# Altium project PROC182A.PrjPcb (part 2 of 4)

## Sheet PROC182A_Decoupling_caps- QSPI Flash.SchDoc: DECOUPLING_CAPS
size 431 x 279 mm; Date: Not shown in title block; ApprovedBy: Not shown in title block; CheckedBy: Not shown in title block; Author: Not shown in title block; CompanyName: Not shown in title block; DrawnBy: Mistral; Engineer: Not shown in title block; Organization: Not shown in title block; Address1: Not shown in title block; Address2: Not shown in title block; Address3: Not shown in title block; Address4: Not shown in title block; DocumentNumber: 2; Revision: Use project parameter SCH_Rev; SheetNumber: 7; SheetTotal: 17; PageSetup: Record=PageOptions¦CenterHorizontal=True¦CenterVertical=True¦PrintScale=1.00¦XCorrection=1.00¦YCorrection=1.00¦PrintKind=0¦BorderSize=5000000¦LeftOffset=0¦BottomOffset=0¦Orientation=2¦PaperLength=1000¦PaperWidth=1000¦Scale=100¦PaperSource=15¦PrintQuality=600¦MediaType=1¦DitherType=10¦PaperKind=Letter¦PrintScaleMode=1
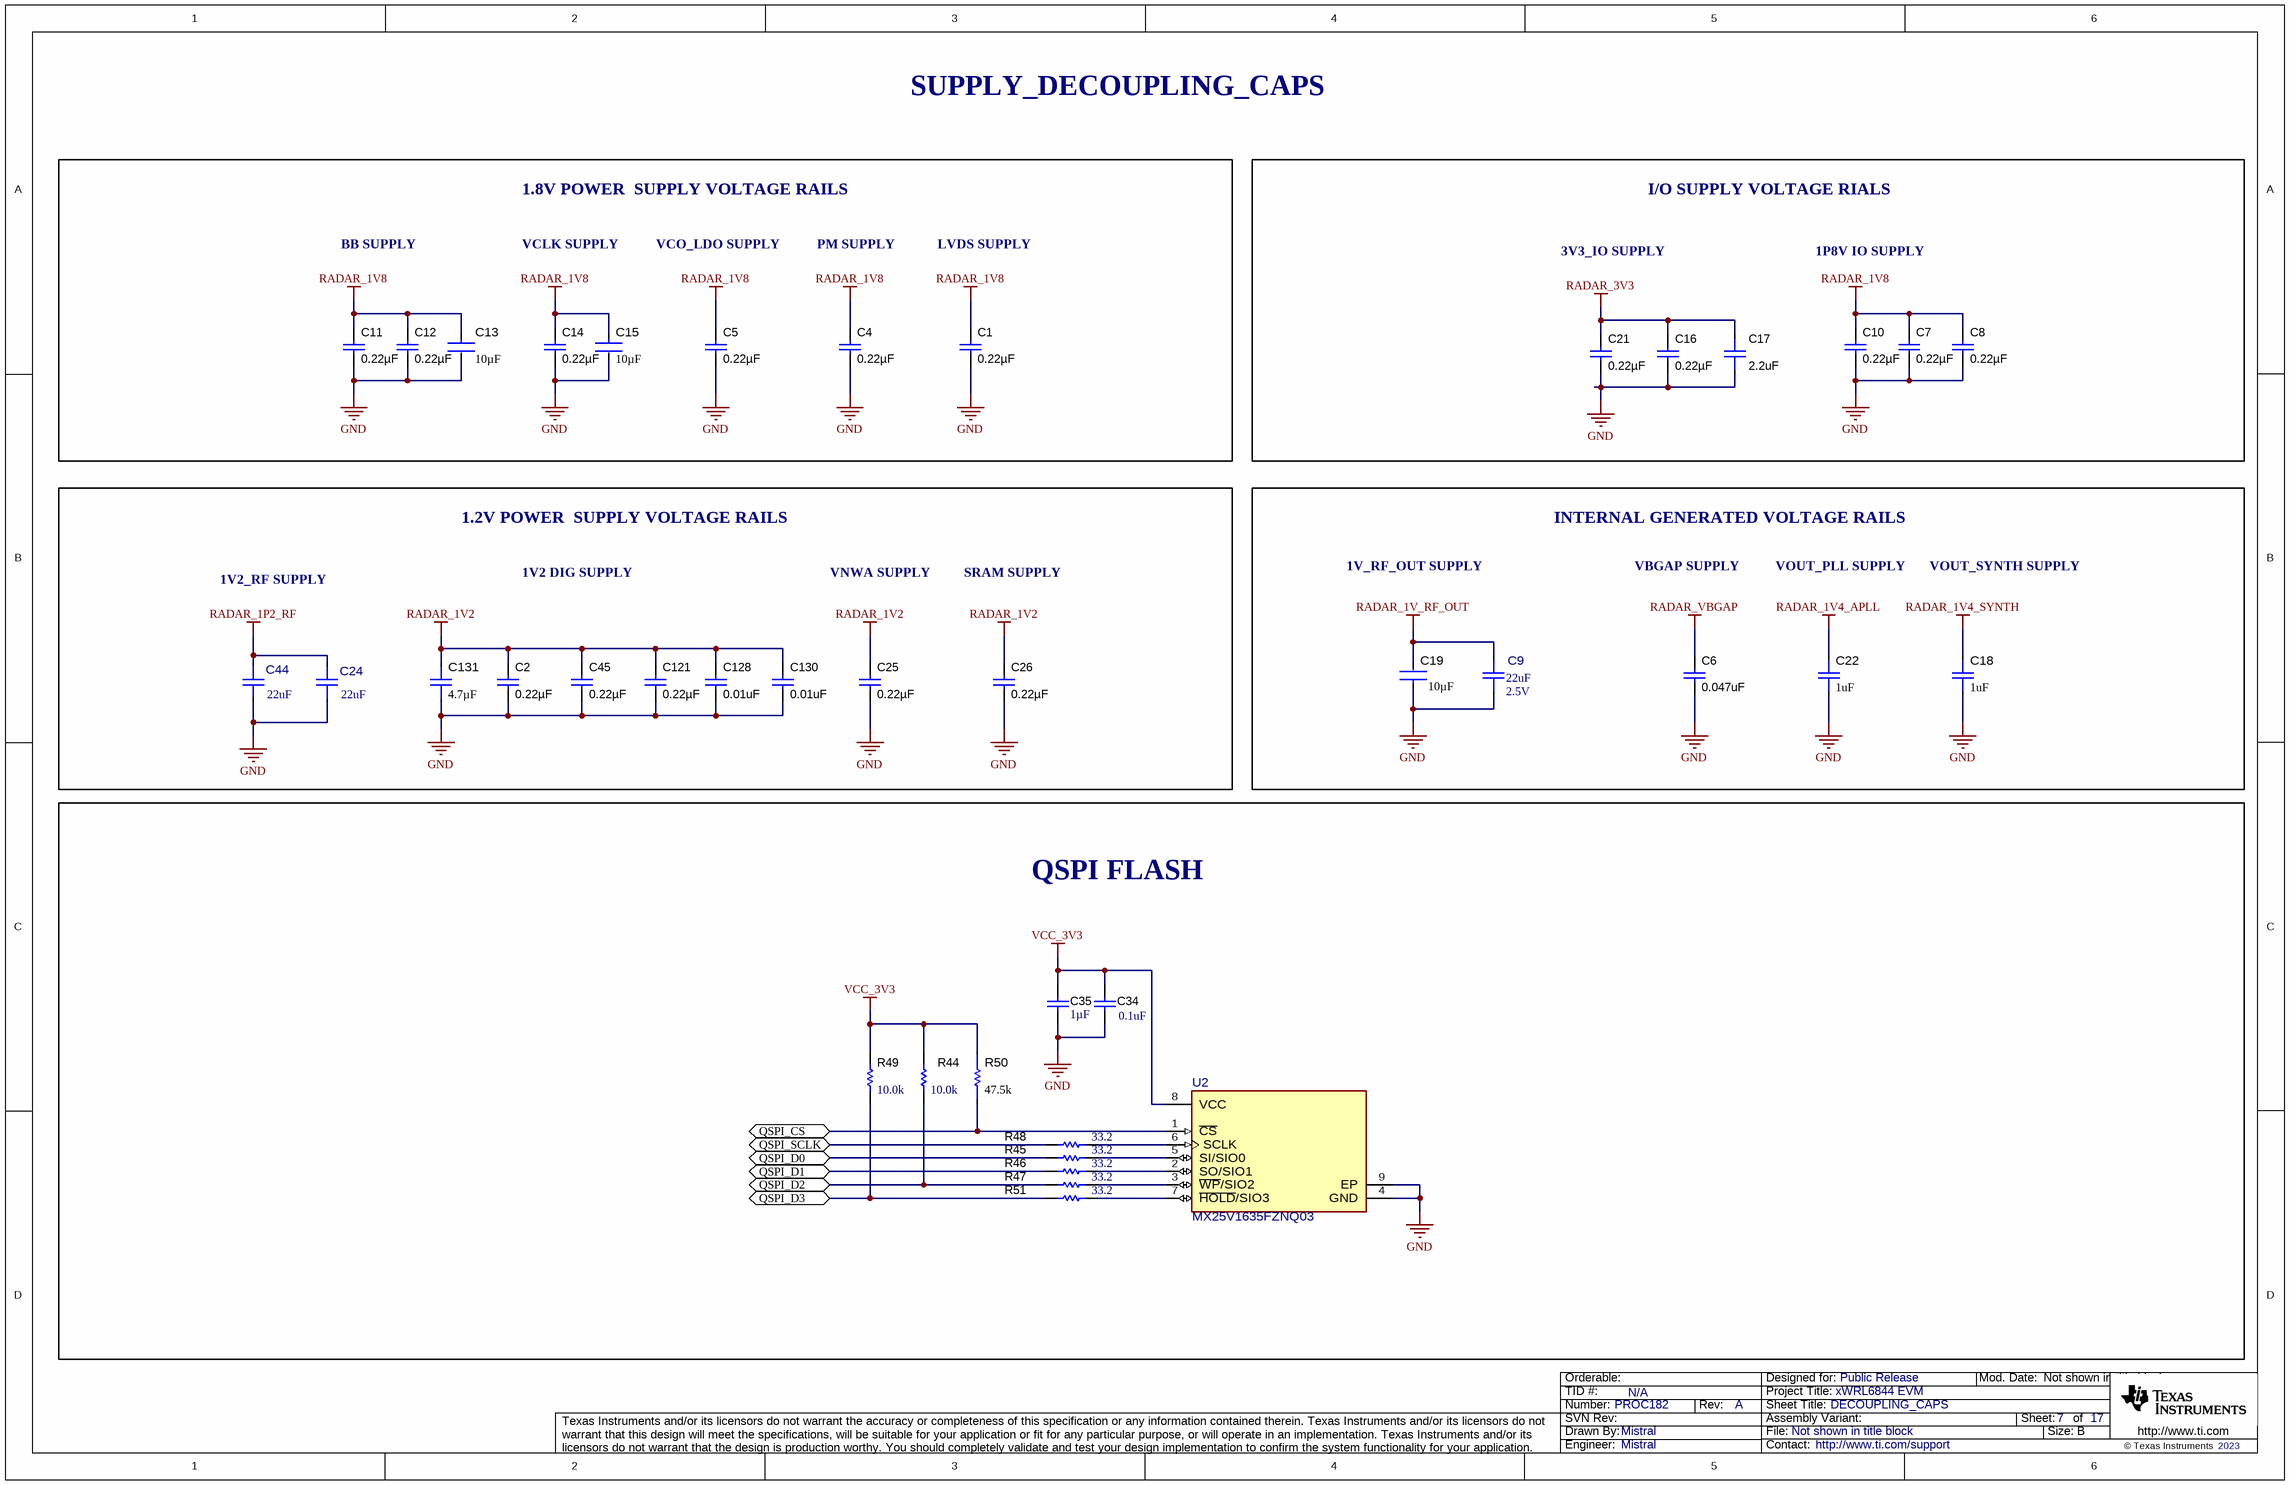
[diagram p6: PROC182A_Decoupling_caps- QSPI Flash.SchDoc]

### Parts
C1  ValueDisplayed: 0.22µF  [0402L]  (hidden comment: GCM155R71C224KE02D)
C2  ValueDisplayed: 0.22µF  [0402L]  (hidden comment: GCM155R71C224KE02D)
C4  ValueDisplayed: 0.22µF  [0402L]  (hidden comment: GCM155R71C224KE02D)
C5  ValueDisplayed: 0.22µF  [0402L]  (hidden comment: GCM155R71C224KE02D)
C6  ValueDisplayed: 0.047uF  [0402L]  (hidden comment: CGA2B3X7R1H473K050BB)
C7  ValueDisplayed: 0.22µF  [0402L]  (hidden comment: GCM155R71C224KE02D)
C8  ValueDisplayed: 0.22µF  [0402L]  (hidden comment: GCM155R71C224KE02D)
C9  ValueDisplayed: 22uF  VDC_V: 2.5V  [FP-GCM188D70E226ME36D_0603-MFG]  (hidden comment: GCM188D70E226ME36D)
C10  ValueDisplayed: 0.22µF  [0402L]  (hidden comment: GCM155R71C224KE02D)
C11  ValueDisplayed: 0.22µF  [0402L]  (hidden comment: GCM155R71C224KE02D)
C12  ValueDisplayed: 0.22µF  [0402L]  (hidden comment: GCM155R71C224KE02D)
C13  Cap_F: 10µF  [FP-GCM188D70J106ME36D_0603-MFG]  (hidden comment: GCM188D70J106ME36D)
C14  ValueDisplayed: 0.22µF  [0402L]  (hidden comment: GCM155R71C224KE02D)
C15  Cap_F: 10µF  [FP-GCM188D70J106ME36D_0603-MFG]  (hidden comment: GCM188D70J106ME36D)
C16  ValueDisplayed: 0.22µF  [0402L]  (hidden comment: GCM155R71C224KE02D)
C17  ValueDisplayed: 2.2uF  [FP-GRT155C71A225KE13D_0402-MFG]  (hidden comment: GRT155C71A225KE13D)
C18  ValueDisplayed: 1uF  [FP-GRT155R70J105KE01D_0402-MFG]  (hidden comment: GRT155R70J105KE01D)
C19  Cap_F: 10µF  [FP-GCM188D70J106ME36D_0603-MFG]  (hidden comment: GCM188D70J106ME36D)
C21  ValueDisplayed: 0.22µF  [0402L]  (hidden comment: GCM155R71C224KE02D)
C22  ValueDisplayed: 1uF  [FP-GRT155R70J105KE01D_0402-MFG]  (hidden comment: GRT155R70J105KE01D)
C24  ValueDisplayed: 22uF  [FP-GCM188D70E226ME36D_0603-MFG]  (hidden comment: GCM188D70E226ME36D)
C25  ValueDisplayed: 0.22µF  [0402L]  (hidden comment: GCM155R71C224KE02D)
C26  ValueDisplayed: 0.22µF  [0402L]  (hidden comment: GCM155R71C224KE02D)
C34  ValueDisplayed: 0.1uF  [0402]  (hidden comment: GCM155R71H104KE02D)
C35  Cap_F: 1µF  [0603]  (hidden comment: CL10B105KA8NNNC)
C44  ValueDisplayed: 22uF  [FP-GCM188D70E226ME36D_0603-MFG]  (hidden comment: GCM188D70E226ME36D)
C45  ValueDisplayed: 0.22µF  [0402L]  (hidden comment: GCM155R71C224KE02D)
C121  ValueDisplayed: 0.22µF  [0402L]  (hidden comment: GCM155R71C224KE02D)
C128  ValueDisplayed: 0.01uF  [0402L]  (hidden comment: GCM155R71E103KA37D)
C130  ValueDisplayed: 0.01uF  [0402L]  (hidden comment: GCM155R71E103KA37D)
C131  Cap_F: 4.7µF  [FP-GCJ21BR71C475KA01L_0805-MFG]  (hidden comment: GCJ21BR71C475KA01L)
R44  value 10.0k  [0402]  (hidden comment: CRCW040210K0FKED)
R45  value 33.2  [0402]  (hidden comment: CRCW040233R2FKED)
R46  value 33.2  [0402]  (hidden comment: CRCW040233R2FKED)
R47  value 33.2  [0402]  (hidden comment: CRCW040233R2FKED)
R48  value 33.2  [0402]  (hidden comment: CRCW040233R2FKED)
R49  value 10.0k  [0402]  (hidden comment: CRCW040210K0FKED)
R50  value 47.5k  [FP-RC0402FR-1047K5L_0402-MFG]  (hidden comment: RC0402FR-1047K5L)
R51  value 33.2  [0402]  (hidden comment: CRCW040233R2FKED)
U2  MX25V1635FZNQ03  [FP-MX25V1635FZNQ03_WSON8-MFG]

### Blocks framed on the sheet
1.8V POWER  SUPPLY VOLTAGE RAILS: C1 C4 C5 C11-C15
I/O SUPPLY VOLTAGE RIALS: C7 C8 C10 C16 C17 C21
1.2V POWER  SUPPLY VOLTAGE RAILS: C2 C24-C26 C44 C45 C121 C128 C130 C131
INTERNAL GENERATED VOLTAGE RAILS: C6 C9 C18 C19 C22
QSPI FLASH: C34 C35 R44-R51 U2

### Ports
QSPI_CS (bidir), QSPI_D0 (bidir), QSPI_D1 (bidir), QSPI_D2 (bidir), QSPI_D3 (bidir), QSPI_SCLK (bidir)

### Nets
GND: C1.1 C2.1 C4.1 C5.1 C6.2 C7.1 C8.1 C9.1 C10.1 C11.1 C12.1 C13.2 C14.1 C15.2 C16.1 C17.1 C18.1 C19.1 C21.1 C22.1 C24.1 C25.1 C26.1 C34.2 C35.1 C44.2 C45.1 C121.1 C128.2 C130.2 C131.1 U2.4(GND) U2.9(EP)
RADAR_1P2_RF: C24.2 C44.1
RADAR_1V2: C2.2 C25.2 C26.2 C45.2 C121.2 C128.1 C130.1 C131.2
RADAR_1V4_APLL: C22.2
RADAR_1V4_SYNTH: C18.2
RADAR_1V8: C1.2 C4.2 C5.2 C7.2 C8.2 C10.2 C11.2 C12.2 C13.1 C14.2 C15.1
RADAR_1V_RF_OUT: C9.2 C19.2
RADAR_3V3: C16.2 C17.2 C21.2
RADAR_VBGAP: C6.1
VCC_3V3: C34.1 C35.2 R44.2 R49.2 R50.1 U2.8(VCC)
QSPI_CS: R50.2 U2.1(~{CS}) ; port QSPI_CS
QSPI_D0: R45.2 ; port QSPI_D0
QSPI_D1: R46.1 ; port QSPI_D1
QSPI_D2: R44.1 R47.1 ; port QSPI_D2
QSPI_D3: R49.1 R51.2 ; port QSPI_D3
QSPI_SCLK: R48.2 ; port QSPI_SCLK
NetR45_1: R45.1 U2.5(SI/SIO0)
NetR46_2: R46.2 U2.2(SO/SIO1)
NetR47_2: R47.2 U2.3(~{WP}/SIO2)
NetR48_1: R48.1 U2.6(SCLK)
NetR51_1: R51.1 U2.7(~{HOLD}/SIO3)

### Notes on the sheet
- SUPPLY_DECOUPLING_CAPS
- BB SUPPLY
- VCLK SUPPLY
- VCO_LDO SUPPLY
- PM SUPPLY
- LVDS SUPPLY
- 3V3_IO SUPPLY
- 1P8V IO SUPPLY
- 1V_RF_OUT SUPPLY
- VBGAP SUPPLY
- VOUT_PLL SUPPLY
- VOUT_SYNTH SUPPLY
- 1V2_RF SUPPLY
- 1V2 DIG SUPPLY
- VNWA SUPPLY
- SRAM SUPPLY

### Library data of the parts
C1 C2 C4 C5 C7 C8 C10-C12 C14 C16 C21 C25 C26 C45 C121 = CMP-0078265-1: CAP, CERM, 0.22 µF, 16 V,+/- 10%, X7R, AEC-Q200 Grade 1, 0402; Manufacturer: MuRata; TaMin_C: -55°C; Polarized: N; SizeAreaWB_mm2: 3; U/M: EA; Value: 0.22uF; TaMax_C: 125°C; SizeZ_mm: 0.6; SizeX_mm: 1; SizeY_mm: 0.5; Cap_Case: 0402; Value2: 16V; CompType: Capacitor; AEC Qualified: Y; Cap_F: 220nF; AEC Category: Q200
C6 = CMP-0006330-2: CAP, CERM, 0.047 uF, 50 V, +/- 10%, X7R, AEC-Q200 Grade 1, 0402; Manufacturer: TDK; Polarized: N; U/M: EA; Cap_F: 47nF; ESR_ohm: 0.06407; Value1: 0.06407 ohm; VDC_V: 50V; IRMS_A: 646.122mA; TaMin_C: -55°C; TaMax_C: 125°C; Cap_Case: 0402; SizeArea_mm2: 0.5; SizeAreaWB_mm2: 3; SizeX_mm: 1; SizeZ_mm: 0.6; AEC Category: Q200; AEC Qualified: Y
C9 C24 C44 = CMP-0048366-1: 22 µF ±20% 2.5V Ceramic Capacitor X7T 0603 (1608 Metric); Manufacturer: Murata; AEC Grade: Grade 1; AEC Qualified: Yes; Cap_F: 22µF; SizeZ_mm: 1mm; TempCo: +22/-33%; Value: 22µF
C13 C15 C19 = CMP-0086534-1: Chip Multilayer Ceramic Capacitors for Automotive; Manufacturer: Murata; Tolerance_%: 20%; SizeZ_mm: 1mm; TempCo: -33+22%; Symbol Name: SYM-GCM188D70J106ME36D; VDC_V: 6.3V; AEC Grade: Grade 1; AEC Qualified: Yes
C17 = CMP-0094968-1: Multi-Layer Ceramic Capacitor 2.2uF 10V X7S ±10% 0402 Paper T/R; Manufacturer: Murata; AEC Grade: Grade 1; Cap_F: 2.2µF; SizeZ_mm: 0.7mm; Value: 2.2µF; AEC Qualified: Yes; TempCo: 22%
C18 C22 = CMP-0088425-1: 1µF ±10% 6.3V Ceramic Capacitor X7R 0402 (1005 Metric); Manufacturer: Murata; AEC Grade: Grade 1; SizeZ_mm: 0.55mm; AEC Qualified: Yes; TempCo: 15%
C34 = CMP-0006356-2: CAP, CERM, 0.1 uF, 50 V, +/- 10%, X7R, AEC-Q200 Grade 1, 0402; Manufacturer: MuRata; TaMin_C: -55°C; Polarized: N; SizeAreaWB_mm2: 3; Value1: Unknown; U/M: EA; Value: 0.1uF; TaMax_C: 125°C; SizeZ_mm: 0.6; SizeX_mm: 1; SizeY_mm: 0.5; Value2: 50V; AEC Qualified: Y; Cap_F: 100nF; AEC Category: Q200
C35 = CMP-0086540-3: CAP, 1uF, 25V, ±10%, X7R, 0603; Manufacturer: Samsung; SizeZ_mm: 0.9mm; AEC Qualified: No; TempCo: 15%; Symbol Name: SYM-CL10B105KA8NNNC
C128 C130 = CMP-0006352-2: CAP, CERM, 0.01 uF, 25 V, +/- 10%, X7R, 0402; Manufacturer: MuRata; TaMin_C: -55°C; Polarized: N; SizeAreaWB_mm2: 3; Value1: Unknown; U/M: EA; Value: 0.01uF; TaMax_C: 125°C; SizeZ_mm: 0.6; SizeX_mm: 1; SizeY_mm: 0.5; Cap_Case: 0402; Value2: 25V; CompType: Capacitor; Cap_F: 10nF; AEC Category: Q200
C131 = CMP-0094778-1: Multilayer Ceramic Capacitors MLCC - SMD/SMT 0805 4.7uF 10%, 16VDC,  X7R 15%; Manufacturer: Murata; AEC Qualified: Yes; Value: 4.7µF; AEC Grade: Grade 1; SizeZ_mm: 1.45mm; VDC_V: 16V
R44 R49 = CMP-0025958-3: RES, 10.0 k, 1%, 0.063 W, AEC-Q200 Grade 0, 0402; Manufacturer: Vishay-Dale; AEC Qualified: Y; Power_W: 63mW; Res_ohm: 10k; SizeZ_mm: 0.6; TempCo: 100 ppm/C; VDC_V: 50V; AEC Category: Q200; AEC Grade: 0; EIA_Code: E96; SizeArea_mm2: 0.5; SizeX_mm: 1; Value2: 0.063W; Value_Code: 10k0
R45-R48 R51 = CMP-0026299-2: RES, 33.2, 1%, 0.063 W, AEC-Q200 Grade 0, 0402; Manufacturer: Vishay-Dale; AEC Qualified: Y; Power_W: 63mW; SizeZ_mm: 0.6; TempCo: 100 ppm/C; VDC_V: 50V; AEC Category: Q200; AEC Grade: 0; EIA_Code: E96; SizeArea_mm2: 0.5; SizeX_mm: 1; Value2: 0.063W; Value_Code: 33R2
R50 = CMP-0120015-1: General Purpose Chip Resistor Thick Film 0402 47.5kOhm 1% Paper T/R; Manufacturer: YAGEO; AEC Qualified: No; Power_W: 63mW; SizeZ_mm: 0.4mm; TempCo: 100ppm/°C; VDC_V: 50V
U2 = CMP-0093403-2: NOR Flash 16Mbit 16M x 1/8M x 2/4M x 4 Serial-SPI 3.3V 8-Pin WSON; Manufacturer: Macronix; TaMax_C: +85°C; AEC Qualified: No; Interface: SPI; Max Supply Voltage: 3.6V; TaMin_C: -40°C; Min Supply Voltage: 2.3V; Memory Type: FLASH,NOR; SizeZ_mm: 0.8mm; Memory Size: 16Mbits; Frequency_Fixed: 80MHz

## Sheet PROC182A_Temp_Current_sensors_EPROM.SchDoc: TEMP_CURRENT_SENSORS_EEPROM
size 431 x 279 mm; Date: Not shown in title block; ApprovedBy: Not shown in title block; CheckedBy: Not shown in title block; Author: Not shown in title block; CompanyName: Not shown in title block; DrawnBy: Mistral; Engineer: Not shown in title block; Organization: Not shown in title block; Address1: Not shown in title block; Address2: Not shown in title block; Address3: Not shown in title block; Address4: Not shown in title block; DocumentNumber: 8; Revision: Use project parameter SCH_Rev; SheetNumber: 8; SheetTotal: 17; PageSetup: Record=PageOptions¦CenterHorizontal=True¦CenterVertical=True¦PrintScale=1.00¦XCorrection=1.00¦YCorrection=1.00¦PrintKind=0¦BorderSize=5000000¦LeftOffset=0¦BottomOffset=0¦Orientation=2¦PaperLength=1000¦PaperWidth=1000¦Scale=100¦PaperSource=15¦PrintQuality=600¦MediaType=1¦DitherType=10¦PaperKind=Letter¦PrintScaleMode=1
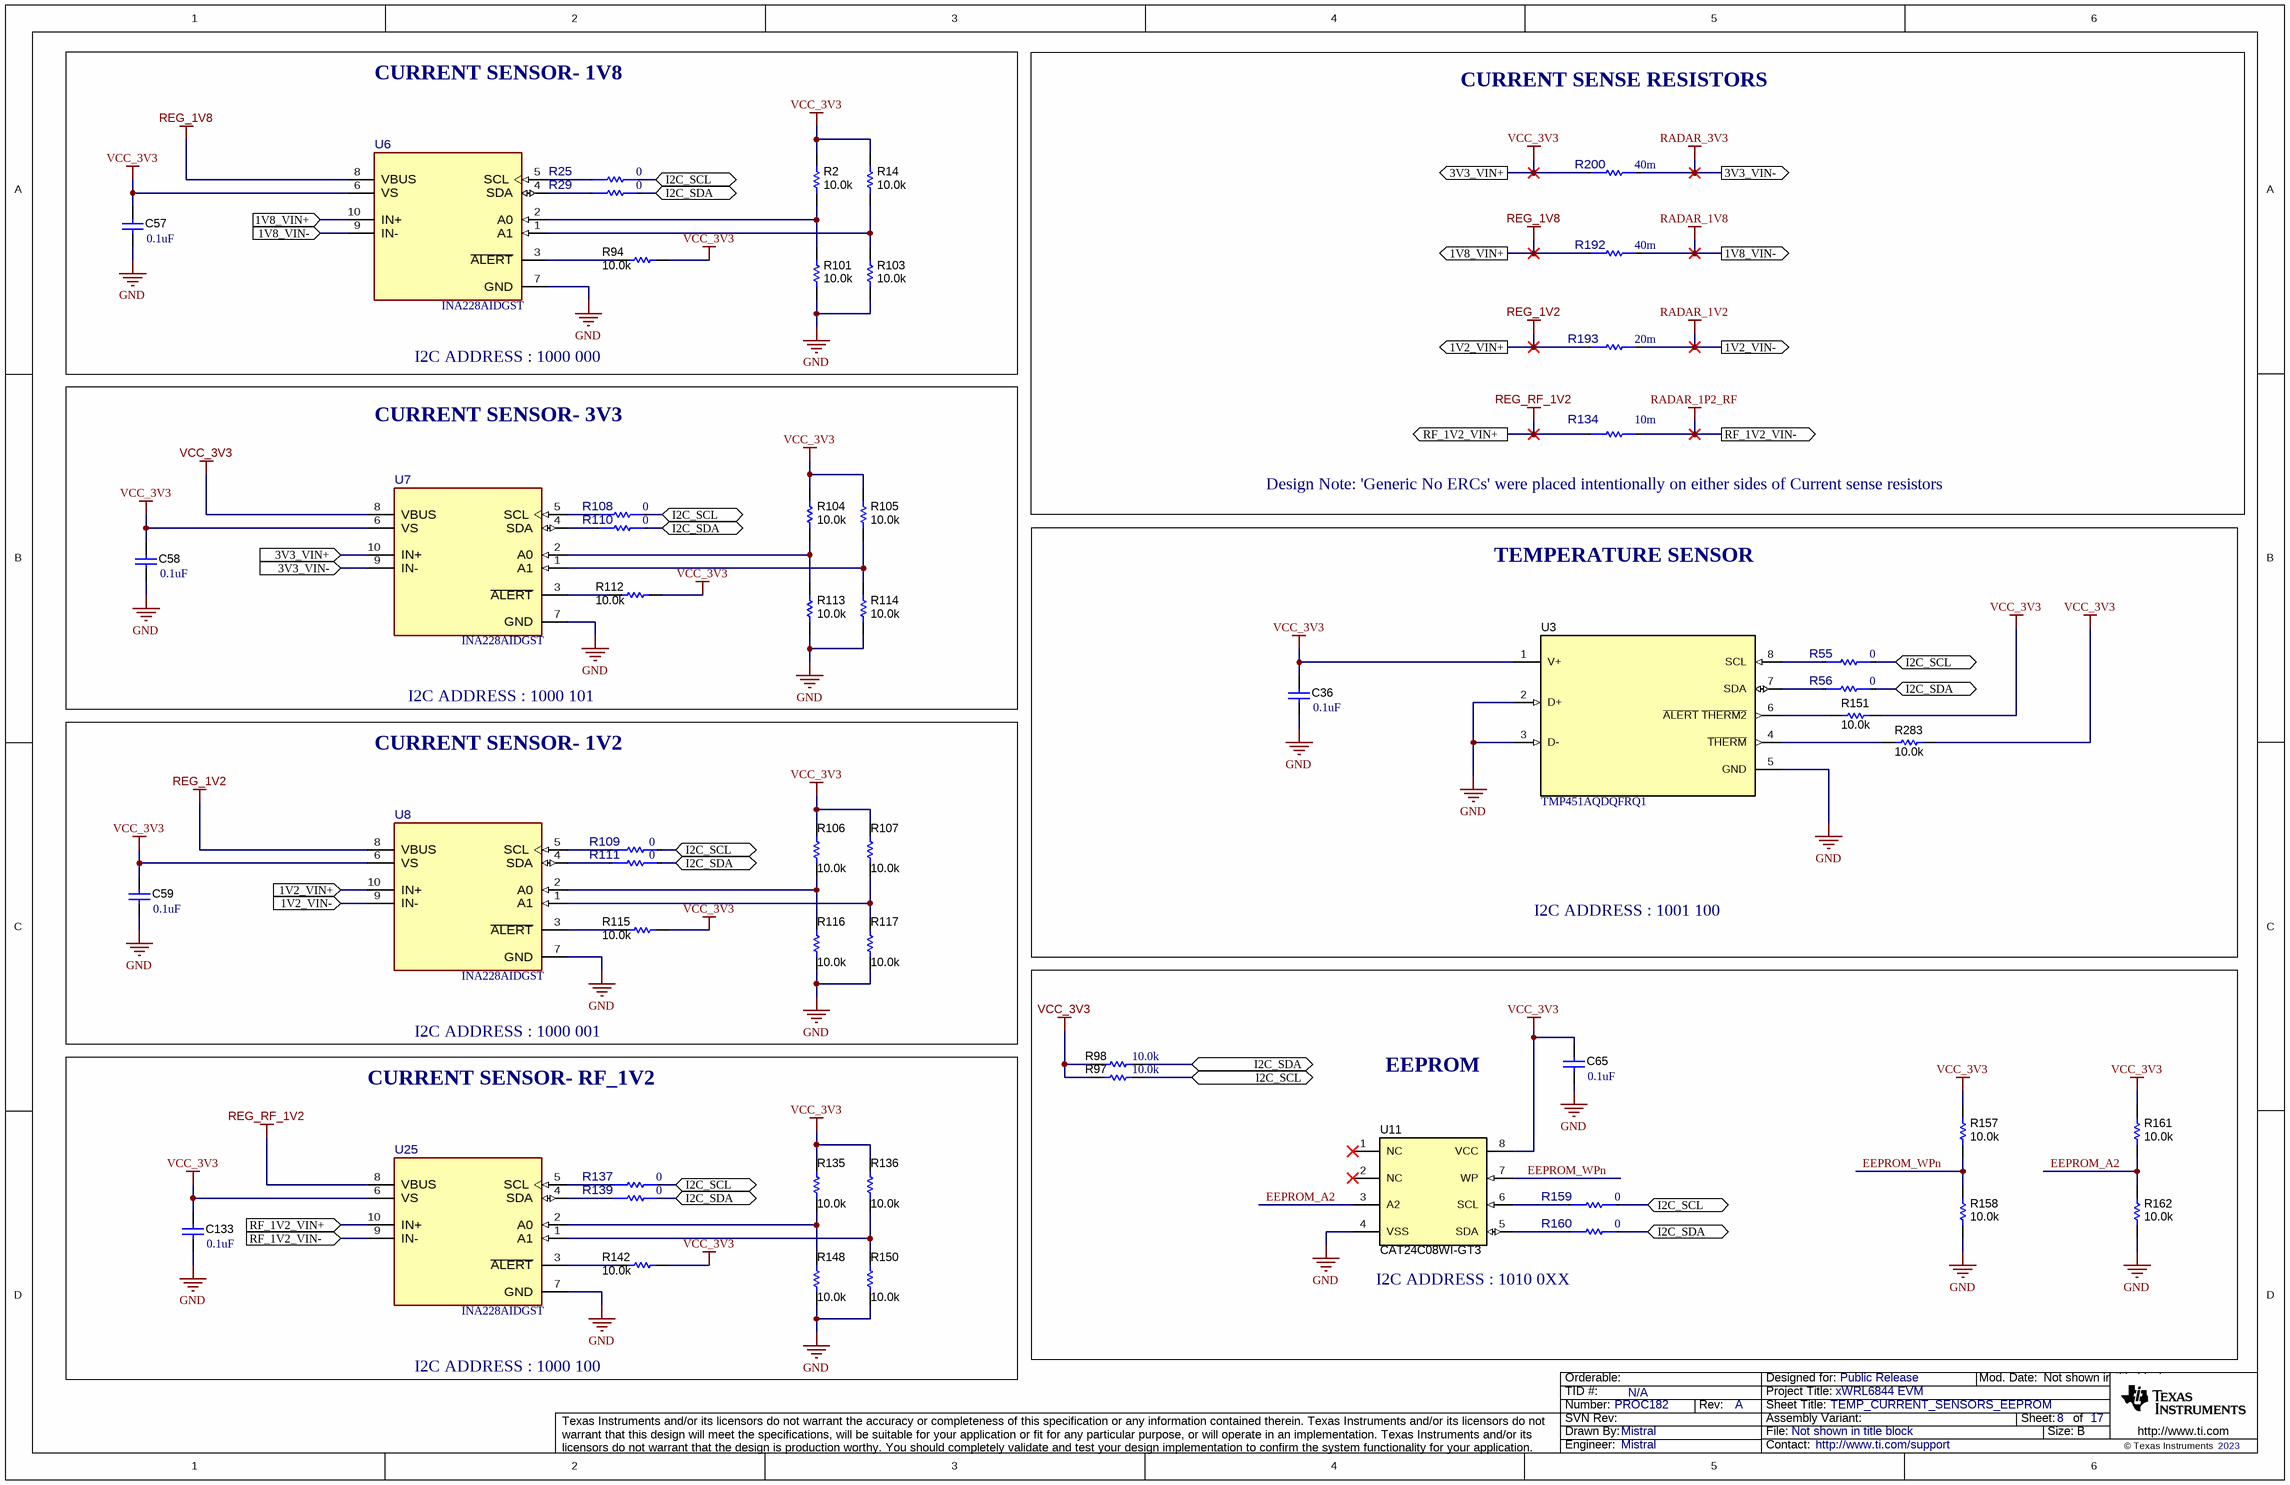
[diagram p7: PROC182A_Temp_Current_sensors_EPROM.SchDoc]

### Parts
C36  ValueDisplayed: 0.1uF  [0402]  (hidden comment: GCM155R71H104KE02D)
C57  ValueDisplayed: 0.1uF  [0402]  (hidden comment: GCM155R71H104KE02D)
C58  ValueDisplayed: 0.1uF  [0402]  (hidden comment: GCM155R71H104KE02D)
C59  ValueDisplayed: 0.1uF  [0402]  (hidden comment: GCM155R71H104KE02D)
C65  ValueDisplayed: 0.1uF  [0402]  (hidden comment: GCM155R71H104KE02D)
C133  ValueDisplayed: 0.1uF  [0402]  (hidden comment: GCM155R71H104KE02D)
R2  ValueDisplayed: 10.0k  [0402L]  (hidden comment: CRCW040210K0FKED)
R14  ValueDisplayed: 10.0k  [0402L]  (hidden comment: CRCW040210K0FKED)
R25  value 0  [FP-ERJ-2GE0R00X_0402-MFG]  (hidden comment: ERJ-2GE0R00X)
R29  value 0  [FP-ERJ-2GE0R00X_0402-MFG]  (hidden comment: ERJ-2GE0R00X)
R55  value 0  [FP-ERJ-2GE0R00X_0402-MFG]  (hidden comment: ERJ-2GE0R00X)
R56  value 0  [FP-ERJ-2GE0R00X_0402-MFG]  (hidden comment: ERJ-2GE0R00X)
R94  ValueDisplayed: 10.0k  [0402L]  (hidden comment: CRCW040210K0FKED)
R97  ValueDisplayed: 10.0k  [0402L]  (hidden comment: CRCW040210K0FKED)
R98  ValueDisplayed: 10.0k  [0402L]  (hidden comment: CRCW040210K0FKED)
R101  ValueDisplayed: 10.0k  [0402L]  (hidden comment: CRCW040210K0FKED)
R103  ValueDisplayed: 10.0k  [0402L]  (hidden comment: CRCW040210K0FKED)
R104  ValueDisplayed: 10.0k  [0402L]  (hidden comment: CRCW040210K0FKED)
R105  ValueDisplayed: 10.0k  [0402L]  (hidden comment: CRCW040210K0FKED)
R106  ValueDisplayed: 10.0k  [0402L]  (hidden comment: CRCW040210K0FKED)
R107  ValueDisplayed: 10.0k  [0402L]  (hidden comment: CRCW040210K0FKED)
R108  value 0  [FP-ERJ-2GE0R00X_0402-MFG]  (hidden comment: ERJ-2GE0R00X)
R109  value 0  [FP-ERJ-2GE0R00X_0402-MFG]  (hidden comment: ERJ-2GE0R00X)
R110  value 0  [FP-ERJ-2GE0R00X_0402-MFG]  (hidden comment: ERJ-2GE0R00X)
R111  value 0  [FP-ERJ-2GE0R00X_0402-MFG]  (hidden comment: ERJ-2GE0R00X)
R112  ValueDisplayed: 10.0k  [0402L]  (hidden comment: CRCW040210K0FKED)
R113  ValueDisplayed: 10.0k  [0402L]  (hidden comment: CRCW040210K0FKED)
R114  ValueDisplayed: 10.0k  [0402L]  (hidden comment: CRCW040210K0FKED)
R115  ValueDisplayed: 10.0k  [0402L]  (hidden comment: CRCW040210K0FKED)
R116  ValueDisplayed: 10.0k  [0402L]  (hidden comment: CRCW040210K0FKED)
R117  ValueDisplayed: 10.0k  [0402L]  (hidden comment: CRCW040210K0FKED)
R134  value 10m  [FP-WSL1206R0100FEB_1206-MFG]  (hidden comment: WSL1206R0100FEB)
R135  ValueDisplayed: 10.0k  [0402L]  (hidden comment: CRCW040210K0FKED)
R136  ValueDisplayed: 10.0k  [0402L]  (hidden comment: CRCW040210K0FKED)
R137  value 0  [FP-ERJ-2GE0R00X_0402-MFG]  (hidden comment: ERJ-2GE0R00X)
R139  value 0  [FP-ERJ-2GE0R00X_0402-MFG]  (hidden comment: ERJ-2GE0R00X)
R142  ValueDisplayed: 10.0k  [0402L]  (hidden comment: CRCW040210K0FKED)
R148  ValueDisplayed: 10.0k  [0402L]  (hidden comment: CRCW040210K0FKED)
R150  ValueDisplayed: 10.0k  [0402L]  (hidden comment: CRCW040210K0FKED)
R151  ValueDisplayed: 10.0k  [0402L]  (hidden comment: CRCW040210K0FKED)
R157  ValueDisplayed: 10.0k  [0402L]  (hidden comment: CRCW040210K0FKED)
R158  ValueDisplayed: 10.0k  [0402L]  (hidden comment: CRCW040210K0FKED)
R159  value 0  [FP-ERJ-2GE0R00X_0402-MFG]  (hidden comment: ERJ-2GE0R00X)
R160  value 0  [FP-ERJ-2GE0R00X_0402-MFG]  (hidden comment: ERJ-2GE0R00X)
R161  ValueDisplayed: 10.0k  [0402L]  (hidden comment: CRCW040210K0FKED)
R162  ValueDisplayed: 10.0k  [0402L]  (hidden comment: CRCW040210K0FKED)
R192  value 40m  [FP-WSL1206R0400FEB_1206-MFG]  (hidden comment: WSL1206R0400FEB)
R193  value 20m  [FP-WSL1206R0200FEB_1206-MFG]  (hidden comment: WSL1206R0200FEB)
R200  value 40m  [FP-WSL1206R0400FEB_1206-MFG]  (hidden comment: WSL1206R0400FEB)
R283  ValueDisplayed: 10.0k  [0402L]  (hidden comment: CRCW040210K0FKED)
U3  TMP451AQDQFRQ1  [DQF0008A]
U6  INA228AIDGST  [DGS0010A-MFG]
U7  INA228AIDGST  [DGS0010A-MFG]
U8  INA228AIDGST  [DGS0010A-MFG]
U11  CAT24C08WI-GT3  [SOIC-8]
U25  INA228AIDGST  [DGS0010A-MFG]

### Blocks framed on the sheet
CURRENT SENSOR- 1V8: C57 R2 R14 R25 R29 R94 R101 R103 U6
CURRENT SENSE RESISTORS: R134 R192 R193 R200
CURRENT SENSOR- 3V3: C58 R104 R105 R108 R110 R112-R114 U7
TEMPERATURE SENSOR: C36 R55 R56 R151 R283 U3
CURRENT SENSOR- 1V2: C59 R106 R107 R109 R111 R115-R117 U8
EEPROM: C65 R97 R98 R157-R162 U11
CURRENT SENSOR- RF_1V2: C133 R135-R137 R139 R142 R148 R150 U25

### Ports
1V2_VIN+ (in), 1V2_VIN+ (out), 1V2_VIN- (in), 1V2_VIN- (out), 1V8_VIN+ (in), 1V8_VIN+ (out), 1V8_VIN- (in), 1V8_VIN- (out), 3V3_VIN+ (in), 3V3_VIN+ (out), 3V3_VIN- (in), 3V3_VIN- (out), I2C_SCL (bidir), I2C_SDA (bidir), RF_1V2_VIN+ (in), RF_1V2_VIN+ (out), RF_1V2_VIN- (in), RF_1V2_VIN- (out)

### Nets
GND: C36.2 C57.2 C58.2 C59.2 C65.2 C133.2 R101.1 R103.1 R113.1 R114.1 R116.1 R117.1 R148.1 R150.1 R158.1 R162.1 U3.2(D+) U3.3(D-) U3.5(GND) U6.7(GND) U7.7(GND) U8.7(GND) U11.4(VSS) U25.7(GND)
RADAR_1P2_RF: R134.2 U25.9(IN-) ; port RF_1V2_VIN-
RADAR_1V2: R193.2 U8.9(IN-) ; port 1V2_VIN-
RADAR_1V8: R192.2 U6.9(IN-) ; port 1V8_VIN-
RADAR_3V3: R200.2 U7.9(IN-) ; port 3V3_VIN-
REG_1V2: R193.1 U8.8(VBUS) U8.10(IN+) ; port 1V2_VIN+
REG_1V8: R192.1 U6.8(VBUS) U6.10(IN+) ; port 1V8_VIN+
REG_RF_1V2: R134.1 U25.8(VBUS) U25.10(IN+) ; port RF_1V2_VIN+
VCC_3V3: C36.1 C57.1 C58.1 C59.1 C65.1 C133.1 R2.2 R14.2 R94.1 R97.2 R98.2 R104.2 R105.2 R106.2 R107.2 R112.1 R115.1 R135.2 R136.2 R142.1 R151.1 R157.2 R161.2 R200.1 R283.1 U3.1(V+) U6.6(VS) U7.6(VS) U7.8(VBUS) U7.10(IN+) U8.6(VS) U11.8(VCC) U25.6(VS) ; port 3V3_VIN+
EEPROM_A2: R161.1 R162.2 U11.3(A2)
EEPROM_WPn: R157.1 R158.2 U11.7(WP)
I2C_SCL: R25.2 R55.2 R97.1 R108.2 R109.2 R137.2 R159.2 ; port I2C_SCL
I2C_SDA: R29.2 R56.2 R98.1 R110.2 R111.2 R139.2 R160.2 ; port I2C_SDA
NetR2_1: R2.1 R101.2 U6.2(A0)
NetR14_1: R14.1 R103.2 U6.1(A1)
NetR25_1: R25.1 U6.5(SCL)
NetR29_1: R29.1 U6.4(SDA)
NetR55_1: R55.1 U3.8(SCL)
NetR56_1: R56.1 U3.7(SDA)
NetR94_2: R94.2 U6.3(~{ALERT})
NetR104_1: R104.1 R113.2 U7.2(A0)
NetR105_1: R105.1 R114.2 U7.1(A1)
NetR106_1: R106.1 R116.2 U8.2(A0)
NetR107_1: R107.1 R117.2 U8.1(A1)
NetR108_1: R108.1 U7.5(SCL)
NetR109_1: R109.1 U8.5(SCL)
NetR110_1: R110.1 U7.4(SDA)
NetR111_1: R111.1 U8.4(SDA)
NetR112_2: R112.2 U7.3(~{ALERT})
NetR115_2: R115.2 U8.3(~{ALERT})
NetR135_1: R135.1 R148.2 U25.2(A0)
NetR136_1: R136.1 R150.2 U25.1(A1)
NetR137_1: R137.1 U25.5(SCL)
NetR139_1: R139.1 U25.4(SDA)
NetR142_2: R142.2 U25.3(~{ALERT})
NetR151_2: R151.2 U3.6(~{ALERT}_~{THERM2})
NetR159_1: R159.1 U11.6(SCL)
NetR160_1: R160.1 U11.5(SDA)
NetR283_2: R283.2 U3.4(~{THERM})

Not connected (* = marked no-connect by the designer): U11 1(NC)* 2(NC)*

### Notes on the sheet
- I2C ADDRESS : 1000 000
- (near R134) Design Note: 'Generic No ERCs' were placed intentionally on either sides of Current sense resistors
- I2C ADDRESS : 1000 101
- I2C ADDRESS : 1001 100
- I2C ADDRESS : 1000 001
- I2C ADDRESS : 1010 0XX
- I2C ADDRESS : 1000 100

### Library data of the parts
C36 C57-C59 C65 C133 = CMP-0006356-2: as C34 on sheet PROC182A_Decoupling_caps- QSPI Flash
R2 R14 R94 R97 R98 R101 R103-R107 R112-R117 R135 R136 R142 R148 R150 R151 R157 R158 R161 R162 R283 = CMP-0025958-3: RES, 10.0 k, 1%, 0.063 W, AEC-Q200 Grade 0, 0402; Manufacturer: Vishay-Dale; Power_W: 63mW; TempCo: 100 ppm/C; Value_Code: 10k0; Value: 10.0k; EIA_Code: E96; Res_ohm: 10k; SizeX_mm: 1; SizeY_mm: 0.5; SizeZ_mm: 0.6; Value2: 0.063W; AEC Qualified: Y; VDC_V: 50V; AEC Category: Q200; AEC Grade: 0
R25 R29 R55 R56 R108-R111 R137 R139 R159 R160 = CMP-0002710-1: 0 Ohms Jumper Chip Resistor 0402 (1005 Metric) Automotive AEC-Q200 Thick Film; Manufacturer: Panasonic; SizeZ_mm: 0.4mm; AEC Qualified: Yes; AEC Grade: Grade 0; Power: 100mW
R134 = CMP-0121430-1: 10 mOhms ±1% 0.25W, 1/4W Chip Resistor Automotive AEC-Q200, Current Sense, Moisture Resistant, Pulse Withstanding Metal Element; Manufacturer: Vishay Dale; AEC Grade: Grade 0; AEC Qualified: Yes; Power_W: 250mW; SizeZ_mm: 0.889mm; TempCo: 75ppm/°C; Category 5A00970A6D5C81C7: Uncategorized; Category 5C6A91606D4187Ad: Resistors; Category 7542B8484461Ae85: Passive Components; Category Cd01000Bfc2916C6: Single Components; Voltage: 50mV
R192 R200 = CMP-0098431-1: 40 mOhms ±1% 0.25W, 1/4W Chip Resistor Automotive AEC-Q200, Current Sense, Moisture Resistant, Pulse Withstanding Metal Element; Manufacturer: Vishay; AEC Grade: Grade 0; AEC Qualified: Yes; Power_W: 250mW; SizeZ_mm: 0.889mm; TempCo: 75ppm/°C
R193 = CMP-0098430-1: Res Metal Strip 1206 0.02 Ohm 1% 1/4W ±75ppm/°C Molded SMD SMD T/R; Manufacturer: Vishay Dale; AEC Grade: Grade 0; AEC Qualified: Yes; Power_W: 250mW; SizeZ_mm: 0.889mm; Category 5C6A91606D4187Ad: Resistors; Category 7542B8484461Ae85: Passive Components; Category Cd01000Bfc2916C6: Single Components
U3 = CMP-0074317-1: Automotive Grade, 1.7V Remote and Local Temp Sensor with N-Factor, Filtering and Series-R Correction, DQF0008A (WSON-8); Alternate Manufacturer: Texas Instruments; SizeAreaWB_mm2: 9.0; U/M: EA; SizeZ_mm: 0.8; SizeX_mm: 2.0; SizeArea_mm2: 4.0; CompType: IC
U6-U8 U25 = CMP-0098432-1: Current Sense Amplifier 1 Circuit 10-VSSOP; Manufacturer: Texas Instruments; SizeZ_mm: 1.1mm; AEC Qualified: No; Input Bias Current: 0.01uA; Input Offset Voltage: 1mV; Max Supply Voltage: 5.5V; Min Supply Voltage: 2.7V; Nominal Supply Current: 640uA; Number Of Channels: 1; Standoff Height: 0.05mm; TaMax_C: +125°C; TaMin_C: -40°C; TJmax_C: +150°C
U11 = CMP-0005309-2: IC, EEPROM, 8KBIT, 400KHZ, 8SOIC; Manufacturer: ON Semiconductor; SizeAreaWB_mm2: 55.131; SizeZ_mm: 1.75; SizeX_mm: 5.99; SizeY_mm: 4.9; SizeArea_mm2: 29.351

## Sheet PROC182A_Analog_Mux_SOP_Ctrl.SchDoc: ANALOG_MUX_SOP_CTRL
size 431 x 279 mm; Date: Not shown in title block; ApprovedBy: Not shown in title block; CheckedBy: Not shown in title block; Author: Not shown in title block; CompanyName: Not shown in title block; DrawnBy: Mistral; Engineer: Not shown in title block; Organization: Not shown in title block; Address1: Not shown in title block; Address2: Not shown in title block; Address3: Not shown in title block; Address4: Not shown in title block; DocumentNumber: 9; Revision: Use project parameter SCH_Rev; SheetNumber: 9; SheetTotal: 17; PageSetup: Record=PageOptions¦CenterHorizontal=True¦CenterVertical=True¦PrintScale=1.00¦XCorrection=1.00¦YCorrection=1.00¦PrintKind=0¦BorderSize=5000000¦LeftOffset=0¦BottomOffset=0¦Orientation=2¦PaperLength=1000¦PaperWidth=1000¦Scale=100¦PaperSource=15¦PrintQuality=600¦MediaType=1¦DitherType=10¦PaperKind=Letter¦PrintScaleMode=1
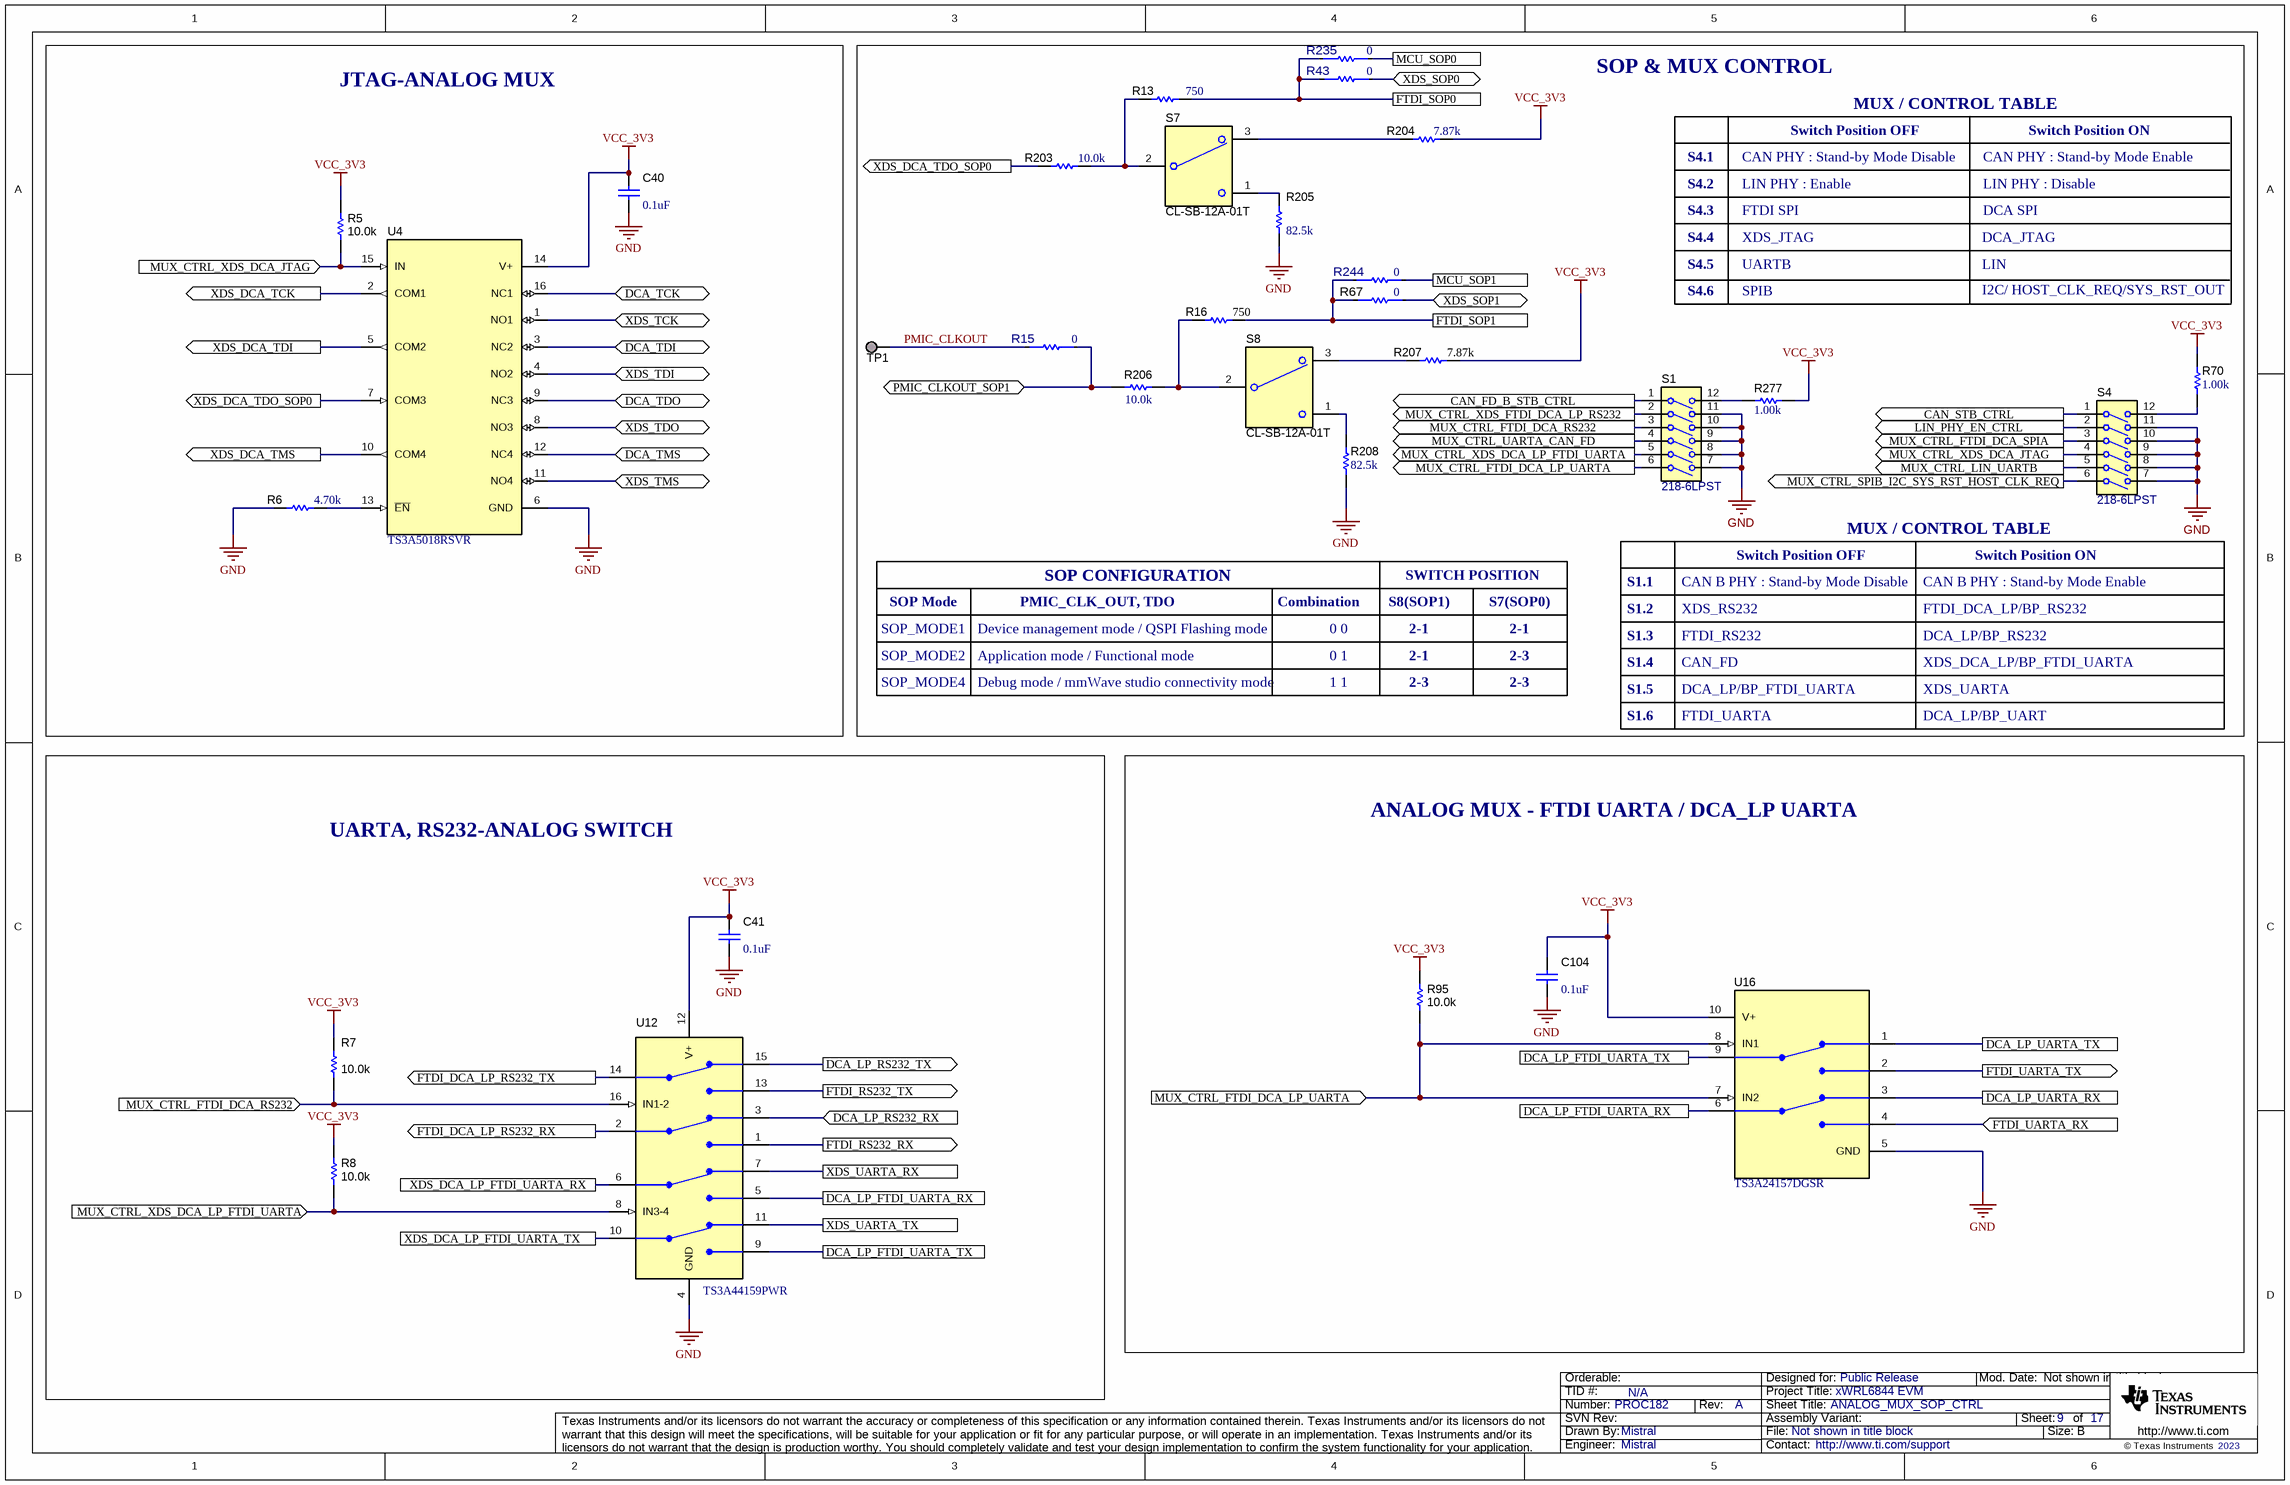
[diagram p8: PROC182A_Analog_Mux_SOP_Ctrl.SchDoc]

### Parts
C40  ValueDisplayed: 0.1uF  [0402]  (hidden comment: GCM155R71H104KE02D)
C41  ValueDisplayed: 0.1uF  [0402]  (hidden comment: GCM155R71H104KE02D)
C104  ValueDisplayed: 0.1uF  [0402]  (hidden comment: GCM155R71H104KE02D)
R5  ValueDisplayed: 10.0k  [0402L]  (hidden comment: CRCW040210K0FKED)
R6  ValueDisplayed: 4.70k  [0402]  (hidden comment: RC0402FR-074K7L)
R7  ValueDisplayed: 10.0k  [0402L]  (hidden comment: CRCW040210K0FKED)
R8  ValueDisplayed: 10.0k  [0402L]  (hidden comment: CRCW040210K0FKED)
R13  ValueDisplayed: 750  [0402L]  (hidden comment: CRCW0402750RFKED)
R15  value 0  [FP-ERJ-2GE0R00X_0402-MFG]  (hidden comment: ERJ-2GE0R00X)
R16  ValueDisplayed: 750  [0402L]  (hidden comment: CRCW0402750RFKED)
R43  value 0  [FP-ERJ-2GE0R00X_0402-MFG]  (hidden comment: ERJ-2GE0R00X)
R67  value 0  [FP-ERJ-2GE0R00X_0402-MFG]  (hidden comment: ERJ-2GE0R00X)
R70  ValueDisplayed: 1.00k  [0402]  (hidden comment: ERJ-2RKF1001X)
R95  ValueDisplayed: 10.0k  [0402L]  (hidden comment: CRCW040210K0FKED)
R203  ValueDisplayed: 10.0k  [0402L]  (hidden comment: CRCW040210K0FKED)
R204  ValueDisplayed: 7.87k  [0402L]  (hidden comment: CRCW04027K87FKED)
R205  ValueDisplayed: 82.5k  [0402L]  (hidden comment: CRCW040282K5FKED)
R206  ValueDisplayed: 10.0k  [0402L]  (hidden comment: CRCW040210K0FKED)
R207  ValueDisplayed: 7.87k  [0402L]  (hidden comment: CRCW04027K87FKED)
R208  ValueDisplayed: 82.5k  [0402L]  (hidden comment: CRCW040282K5FKED)
R235  value 0  [FP-ERJ-2GE0R00X_0402-MFG]  (hidden comment: ERJ-2GE0R00X)
R244  value 0  [FP-ERJ-2GE0R00X_0402-MFG]  (hidden comment: ERJ-2GE0R00X)
R277  ValueDisplayed: 1.00k  [0402]  (hidden comment: ERJ-2RKF1001X)
S1  218-6LPST  [SW_218-6LPST]
S4  218-6LPST  [SW_218-6LPST]
S7  CL-SB-12A-01T  [SW_CL-SB-12A-01]
S8  CL-SB-12A-01T  [SW_CL-SB-12A-01]
TP1  TESTPOINT  [TP_25MIL-SMT]  (value not drawn)  (no BOM)
U4  TS3A5018RSVR  [RSV0016A]
U12  TS3A44159PWR  [PW0016A_N]
U16  TS3A24157DGSR  [DGS0010A_N]

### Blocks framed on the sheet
JTAG-ANALOG MUX: C40 R5 R6 U4
SOP & MUX CONTROL: R13 R15 R16 R43 R67 R70 R203-R208 R235 R244 R277 S1 S4 S7 S8 TP1
UARTA, RS232-ANALOG SWITCH: C41 R7 R8 U12
ANALOG MUX - FTDI UARTA / DCA_LP UARTA: C104 R95 U16

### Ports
CAN_FD_B_STB_CTRL (out), CAN_STB_CTRL (out), DCA_LP_FTDI_UARTA_RX, DCA_LP_FTDI_UARTA_TX, DCA_LP_RS232_RX (in), DCA_LP_RS232_TX (out), DCA_LP_UARTA_RX, DCA_LP_UARTA_TX, DCA_TCK (bidir), DCA_TDI (bidir), DCA_TDO (bidir), DCA_TMS (bidir), FTDI_DCA_LP_RS232_RX (out), FTDI_DCA_LP_RS232_TX (out), FTDI_RS232_RX (out), FTDI_RS232_TX (out), FTDI_SOP0, FTDI_SOP1, FTDI_UARTA_RX (in), FTDI_UARTA_TX (out), LIN_PHY_EN_CTRL (out), MCU_SOP0, MCU_SOP1, MUX_CTRL_FTDI_DCA_LP_UARTA (in), MUX_CTRL_FTDI_DCA_LP_UARTA (out), MUX_CTRL_FTDI_DCA_RS232 (in), MUX_CTRL_FTDI_DCA_RS232 (out), MUX_CTRL_FTDI_DCA_SPIA (out), MUX_CTRL_LIN_UARTB (out), MUX_CTRL_SPIB_I2C_SYS_RST_HOST_CLK_REQ (out), MUX_CTRL_UARTA_CAN_FD (out), MUX_CTRL_XDS_DCA_JTAG (in), MUX_CTRL_XDS_DCA_JTAG (out), MUX_CTRL_XDS_DCA_LP_FTDI_UARTA (in), MUX_CTRL_XDS_DCA_LP_FTDI_UARTA (out), MUX_CTRL_XDS_FTDI_DCA_LP_RS232 (out), PMIC_CLKOUT_SOP1 (bidir), XDS_DCA_LP_FTDI_UARTA_RX, XDS_DCA_LP_FTDI_UARTA_TX, XDS_DCA_TCK (out), XDS_DCA_TDI (out), XDS_DCA_TDO_SOP0 (out), XDS_DCA_TMS (out), XDS_SOP0 (bidir), XDS_SOP1 (bidir), XDS_TCK (bidir), XDS_TDI (bidir), XDS_TDO (bidir), XDS_TMS (bidir), XDS_UARTA_RX, XDS_UARTA_TX

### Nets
GND: C40.2 C41.2 C104.2 R6.1 R205.1 R208.1 S1.7(6A) S1.8(5A) S1.9(4A) S1.10(3A) S1.11(2A) S4.7(6A) S4.8(5A) S4.9(4A) S4.10(3A) S4.11(2A) U4.6(GND) U12.4(GND) U16.5(GND)
VCC_3V3: C40.1 C41.1 C104.1 R5.2 R7.2 R8.2 R70.2 R95.2 R204.2 R207.2 R277.2 U4.14(V+) U12.12(V+) U16.10(V+)
CAN_FD_B_STB_CTRL: S1.1 ; port CAN_FD_B_STB_CTRL
CAN_STB_CTRL: S4.1 ; port CAN_STB_CTRL
DCA_LP_FTDI_UARTA_RX: U12.5(NO3) U16.6(COM2) ; port DCA_LP_FTDI_UARTA_RX
DCA_LP_FTDI_UARTA_TX: U12.9(NO4) U16.9(COM1) ; port DCA_LP_FTDI_UARTA_TX
DCA_LP_RS232_RX: U12.3(NC2) ; port DCA_LP_RS232_RX
DCA_LP_RS232_TX: U12.15(NC1) ; port DCA_LP_RS232_TX
DCA_LP_UARTA_RX: U16.3(NC2) ; port DCA_LP_UARTA_RX
DCA_LP_UARTA_TX: U16.1(NC1) ; port DCA_LP_UARTA_TX
DCA_TCK: U4.16(NC1) ; port DCA_TCK
DCA_TDI: U4.3(NC2) ; port DCA_TDI
DCA_TDO: U4.9(NC3) ; port DCA_TDO
DCA_TMS: U4.12(NC4) ; port DCA_TMS
FTDI_DCA_LP_RS232_RX: U12.2(COM2) ; port FTDI_DCA_LP_RS232_RX
FTDI_DCA_LP_RS232_TX: U12.14(COM1) ; port FTDI_DCA_LP_RS232_TX
FTDI_RS232_RX: U12.1(NO2) ; port FTDI_RS232_RX
FTDI_RS232_TX: U12.13(NO1) ; port FTDI_RS232_TX
FTDI_SOP0: R13.1 R43.2 R235.1 ; port FTDI_SOP0
FTDI_SOP1: R16.1 R67.2 R244.1 ; port FTDI_SOP1
FTDI_UARTA_RX: U16.4(NO2) ; port FTDI_UARTA_RX
FTDI_UARTA_TX: U16.2(NO1) ; port FTDI_UARTA_TX
LIN_PHY_EN_CTRL: S4.2 ; port LIN_PHY_EN_CTRL
MCU_SOP0: R235.2 ; port MCU_SOP0
MCU_SOP1: R244.2 ; port MCU_SOP1
MUX_CTRL_FTDI_DCA_LP_UARTA: R95.1 S1.6 U16.7(IN2) U16.8(IN1) ; port MUX_CTRL_FTDI_DCA_LP_UARTA
MUX_CTRL_FTDI_DCA_RS232: R7.1 S1.3 U12.16(IN1-2) ; port MUX_CTRL_FTDI_DCA_RS232
MUX_CTRL_FTDI_DCA_SPIA: S4.3 ; port MUX_CTRL_FTDI_DCA_SPIA
MUX_CTRL_LIN_UARTB: S4.5 ; port MUX_CTRL_LIN_UARTB
MUX_CTRL_SPIB_I2C_SYS_RST_HOST_CLK_REQ: S4.6 ; port MUX_CTRL_SPIB_I2C_SYS_RST_HOST_CLK_REQ
MUX_CTRL_UARTA_CAN_FD: S1.4 ; port MUX_CTRL_UARTA_CAN_FD
MUX_CTRL_XDS_DCA_JTAG: R5.1 S4.4 U4.15(IN) ; port MUX_CTRL_XDS_DCA_JTAG
MUX_CTRL_XDS_DCA_LP_FTDI_UARTA: R8.1 S1.5 U12.8(IN3-4) ; port MUX_CTRL_XDS_DCA_LP_FTDI_UARTA
MUX_CTRL_XDS_FTDI_DCA_LP_RS232: S1.2 ; port MUX_CTRL_XDS_FTDI_DCA_LP_RS232
PMIC_CLKOUT: R15.2 TP1.1
PMIC_CLKOUT_SOP1: R15.1 R206.1 ; port PMIC_CLKOUT_SOP1
XDS_DCA_LP_FTDI_UARTA_RX: U12.6(COM3) ; port XDS_DCA_LP_FTDI_UARTA_RX
XDS_DCA_LP_FTDI_UARTA_TX: U12.10(COM4) ; port XDS_DCA_LP_FTDI_UARTA_TX
XDS_DCA_TCK: U4.2(COM1) ; port XDS_DCA_TCK
XDS_DCA_TDI: U4.5(COM2) ; port XDS_DCA_TDI
XDS_DCA_TDO_SOP0: R203.1 U4.7(COM3) ; port XDS_DCA_TDO_SOP0
XDS_DCA_TMS: U4.10(COM4) ; port XDS_DCA_TMS
XDS_SOP0: R43.1 ; port XDS_SOP0
XDS_SOP1: R67.1 ; port XDS_SOP1
XDS_TCK: U4.1(NO1) ; port XDS_TCK
XDS_TDI: U4.4(NO2) ; port XDS_TDI
XDS_TDO: U4.8(NO3) ; port XDS_TDO
XDS_TMS: U4.11(NO4) ; port XDS_TMS
XDS_UARTA_RX: U12.7(NC3) ; port XDS_UARTA_RX
XDS_UARTA_TX: U12.11(NC4) ; port XDS_UARTA_TX
NetR6_2: R6.2 U4.13(~{EN})
NetR13_2: R13.2 R203.2 S7.2(COM)
NetR16_2: R16.2 R206.2 S8.2(COM)
NetR70_1: R70.1 S4.12(1A)
NetR204_1: R204.1 S7.3
NetR205_2: R205.2 S7.1
NetR207_1: R207.1 S8.3
NetR208_2: R208.2 S8.1
NetR277_1: R277.1 S1.12(1A)

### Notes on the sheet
- MUX / CONTROL TABLE
- S4.1
- CAN PHY : Stand-by Mode Disable
- Switch Position OFF
- CAN PHY : Stand-by Mode Enable
- Switch Position ON
- S4.2
- S4.3
- S4.4
- LIN PHY : Enable
- FTDI SPI
- XDS_JTAG
- DCA_JTAG
- LIN PHY : Disable
- DCA SPI
- S4.5
- S4.6
- UARTB
- SPIB
- LIN
- I2C/ HOST_CLK_REQ/SYS_RST_OUT
- SOP CONFIGURATION
- SWITCH POSITION
- SOP_MODE1
- SOP Mode
- Device management mode / QSPI Flashing mode
- PMIC_CLK_OUT, TDO
- Combination
- 0 0
- S8(SOP1)
- 2-1
- S7(SOP0)
- S1.3
- S1.2
- S1.1
- FTDI_RS232
- XDS_RS232
- CAN B PHY : Stand-by Mode Disable
- DCA_LP/BP_RS232
- FTDI_DCA_LP/BP_RS232
- CAN B PHY : Stand-by Mode Enable
- SOP_MODE2
- SOP_MODE4
- Application mode / Functional mode
- Debug mode / mmWave studio connectivity mode
- 0 1
- 1 1
- 2-3
- S1.4
- S1.5
- DCA_LP/BP_FTDI_UARTA
- CAN_FD
- XDS_UARTA
- XDS_DCA_LP/BP_FTDI_UARTA
- S1.6
- FTDI_UARTA
- DCA_LP/BP_UART

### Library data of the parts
C40 C41 C104 = CMP-0006356-2: CAP, CERM, 0.1 uF, 50 V, +/- 10%, X7R, AEC-Q200 Grade 1, 0402; Manufacturer: MuRata; TaMin_C: -55°C; Polarized: N; SizeAreaWB_mm2: 3; U/M: EA; Value: 0.1uF; TaMax_C: 125°C; SizeZ_mm: 0.6; SizeX_mm: 1; SizeY_mm: 0.5; Value2: 50V; AEC Qualified: Y; Cap_F: 100nF; AEC Category: Q200; Value1: Unknown
R5 R7 R8 R95 R203 R206 = CMP-0025958-3: as R2 on sheet PROC182A_Temp_Current_sensors_EPROM
R6 = CMP-0026739-1: RES, 4.70 k, 1%, 0.0625 W, 0402; Manufacturer: Yageo America; Power_W: 62.5mW; TempCo: 100 ppm/C; Value_Code: 4k70; Value: 4.70k; Res_ohm: 4.7k; SizeX_mm: 1; SizeY_mm: 0.5; SizeZ_mm: 0.6; AEC Qualified: N; VDC_V: 50V; AEC Category: Q200; U/M: EA
R13 R16 = CMP-0026542-2: RES, 750, 1%, 0.063 W, AEC-Q200 Grade 0, 0402; Manufacturer: Vishay-Dale; Power_W: 63mW; TempCo: 100 ppm/C; Value_Code: 750R; Value: 750; EIA_Code: E96; SizeX_mm: 1; SizeY_mm: 0.5; SizeZ_mm: 0.6; Value2: 0.063W; AEC Qualified: Y; VDC_V: 50V; AEC Grade: 0; AEC Category: Q200
R15 R43 R67 R235 R244 = CMP-0002710-1: as R25 on sheet PROC182A_Temp_Current_sensors_EPROM
R70 R277 = CMP-0026657-1: RES, 1.00 k, 1%, 0.1 W, 0402; Manufacturer: Panasonic; Power_W: 100mW; TempCo: 100 ppm/C; Value_Code: 1k00; Value: 1.00k; EIA_Code: E96; Res_ohm: 1k; SizeX_mm: 1; SizeY_mm: 0.5; SizeZ_mm: 0.6; Value2: 0.1W; VDC_V: 50V; AEC Category: Q200; U/M: EA
R204 R207 = CMP-0026557-2: RES, 7.87 k, 1%, 0.063 W, AEC-Q200 Grade 0, 0402; Manufacturer: Vishay-Dale; Power_W: 63mW; TempCo: 100 ppm/C; Value_Code: 7k87; Value: 7.87k; EIA_Code: E96; SizeX_mm: 1; SizeY_mm: 0.5; SizeZ_mm: 0.6; Value2: 0.063W; AEC Qualified: Y; VDC_V: 50V; AEC Grade: 0; AEC Category: Q200
R205 R208 = CMP-0026574-2: RES, 82.5 k, 1%, 0.063 W, AEC-Q200 Grade 0, 0402; Manufacturer: Vishay-Dale; Power_W: 63mW; TempCo: 100 ppm/C; Value_Code: 82k5; Value: 82.5k; EIA_Code: E96; SizeX_mm: 1; SizeY_mm: 0.5; SizeZ_mm: 0.6; Value2: 0.063W; AEC Qualified: Y; VDC_V: 50V; AEC Grade: 0; AEC Category: Q200
S1 S4 = CMP-0002304-1: Switch, SPST, Slide, Off-On, 6 Pos, 0.025A, 24V, SMD; Manufacturer: CTS Electrocomponents; CurrentRating_mA: 25A; PositionCount: 6; SizeX_mm: 8.44; SizeY_mm: 8.79; SizeZ_mm: 2.65; SizeArea_mm2: 74.1876; SizeAreaWB_mm2: 112.6476
S7 S8 = CMP-0002183-2: Switch, Slide, SPDT, 0.2A, J Lead, SMD; Manufacturer: Copal Electronics; CurrentRating_mA: 200A; SwitchFunction: On-On; VDC_V: 12V; PositionCount: 2
TP1 = CMP-0078143-3: TEST POINT.  No entry in BOM.
U4 = CMP-0067415-1: 10-Ohm Quad SPDT Analog Switch, RSV0016A (UQFN-16); Alternate Manufacturer: Texas Instruments; SizeAreaWB_mm2: 10.08; U/M: EA; SizeZ_mm: 0.55; SizeX_mm: 1.8; SizeY_mm: 2.6; SizeArea_mm2: 4.68; CompType: IC
U12 = CMP-0067412-1: 0.45-Ohm Quad SPDT Analog Switch Quad-Channel 2:1 Multiplexer/Demultiplexer with Two Controls, PW0016A (TSSOP-16); Alternate Manufacturer: Texas Instruments; SizeAreaWB_mm2: 58.8; U/M: EA; SizeZ_mm: 1.2; SizeX_mm: 6.4; SizeY_mm: 5.0; SizeArea_mm2: 32.0; CompType: IC
U16 = CMP-0067410-1: 0.65 Ohm Dual SPDT Analog Switch Dual-Channel 2:1 Multiplexer/Demultiplexer, DGS0010A (VSSOP-10); Alternate Manufacturer: Texas Instruments; SizeAreaWB_mm2: 23.6; U/M: EA; SizeZ_mm: 1.1; SizeX_mm: 4.9; SizeY_mm: 3.0; SizeArea_mm2: 14.7; CompType: IC

## Sheet PROC182A_Analog_MUX_SPI.SchDoc: Analog Mux SPI and UART B
size 431 x 279 mm; Date: Not shown in title block; ApprovedBy: Not shown in title block; CheckedBy: Not shown in title block; Author: Not shown in title block; CompanyName: Not shown in title block; DrawnBy: Mistral; Engineer: Not shown in title block; Organization: Not shown in title block; Address1: Not shown in title block; Address2: Not shown in title block; Address3: Not shown in title block; Address4: Not shown in title block; DocumentNumber: 3; Revision: Use project parameter SCH_Rev; SheetNumber: 10; SheetTotal: 17; PageSetup: Record=PageOptions¦CenterHorizontal=True¦CenterVertical=True¦PrintScale=1.00¦XCorrection=1.00¦YCorrection=1.00¦PrintKind=0¦BorderSize=5000000¦LeftOffset=0¦BottomOffset=0¦Orientation=2¦PaperLength=1000¦PaperWidth=1000¦Scale=100¦PaperSource=15¦PrintQuality=600¦MediaType=1¦DitherType=10¦PaperKind=Letter¦PrintScaleMode=1
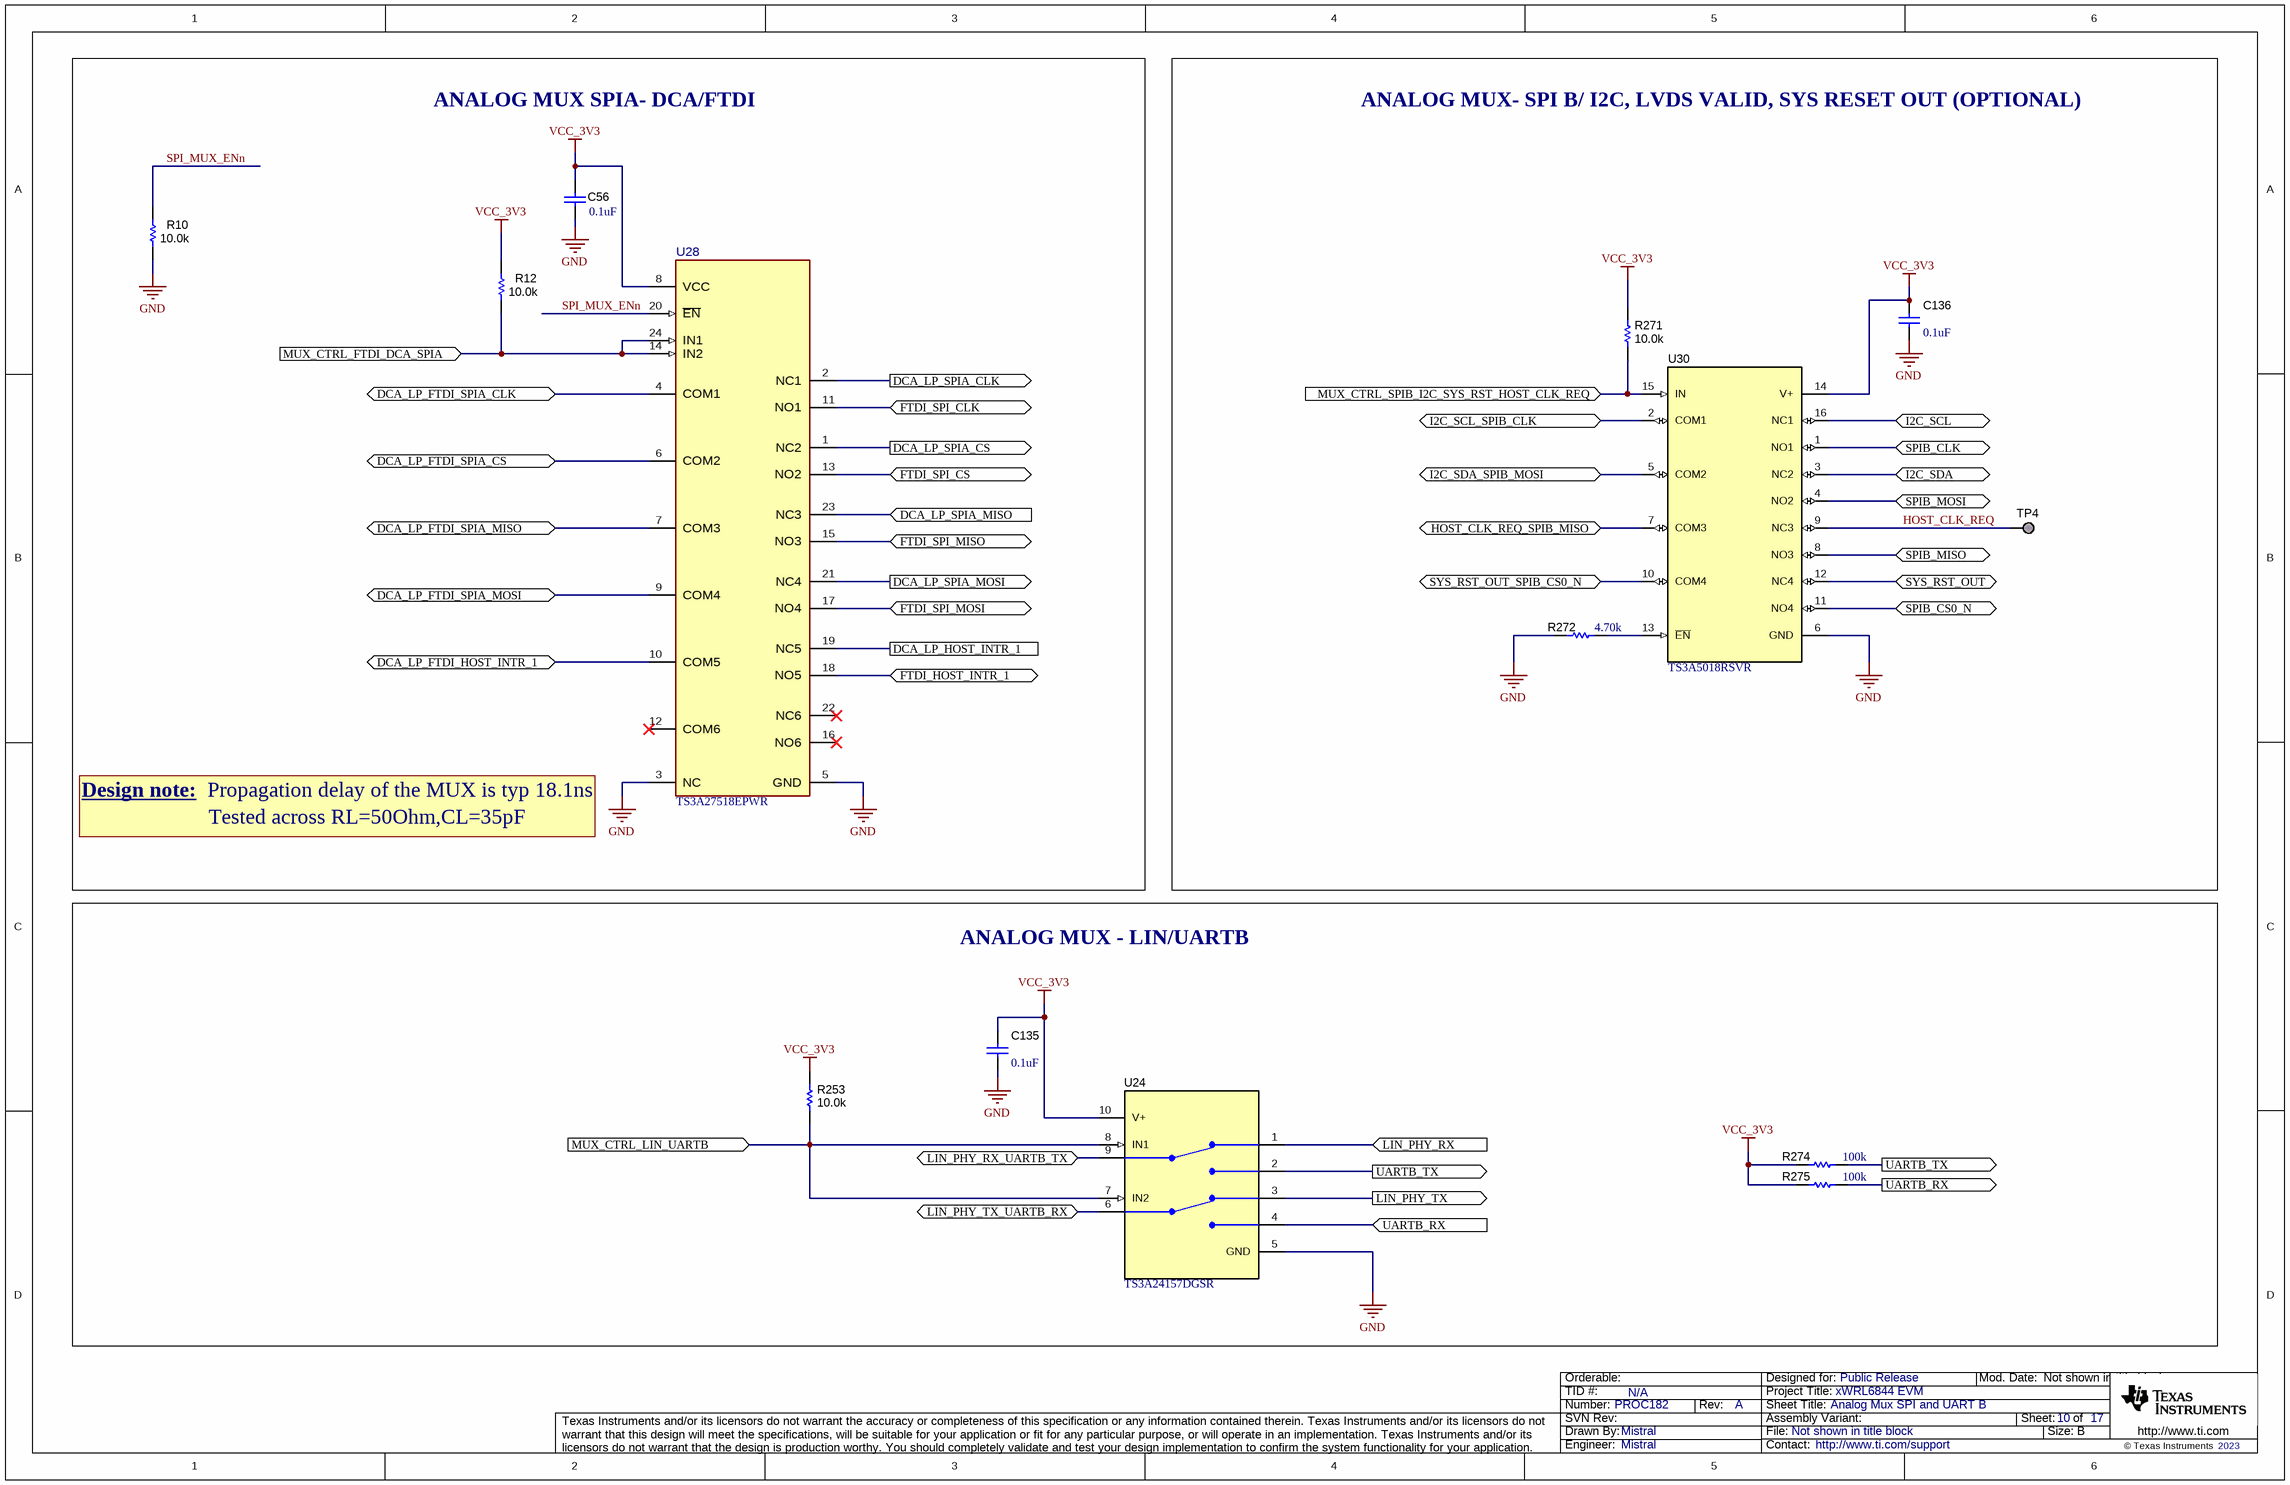
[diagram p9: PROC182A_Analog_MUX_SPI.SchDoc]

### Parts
C56  ValueDisplayed: 0.1uF  [0402]  (hidden comment: GCM155R71H104KE02D)
C135  ValueDisplayed: 0.1uF  [0402]  (hidden comment: GCM155R71H104KE02D)
C136  ValueDisplayed: 0.1uF  [0402]  (hidden comment: GCM155R71H104KE02D)
R10  ValueDisplayed: 10.0k  [0402L]  (hidden comment: CRCW040210K0FKED)
R12  ValueDisplayed: 10.0k  [0402L]  (hidden comment: CRCW040210K0FKED)
R253  ValueDisplayed: 10.0k  [0402L]  (hidden comment: CRCW040210K0FKED)
R271  ValueDisplayed: 10.0k  [0402L]  (hidden comment: CRCW040210K0FKED)
R272  ValueDisplayed: 4.70k  [0402]  (hidden comment: RC0402FR-074K7L)
R274  ValueDisplayed: 100k  [0402L]  (hidden comment: CRCW0402100KFKED)
R275  ValueDisplayed: 100k  [0402L]  (hidden comment: CRCW0402100KFKED)
TP4  TESTPOINT  [TP_25MIL-SMT]  (value not drawn)  (no BOM)
U24  TS3A24157DGSR  [DGS0010A_N]
U28  TS3A27518EPWR  [PW0024A-MFG]
U30  TS3A5018RSVR  [RSV0016A]

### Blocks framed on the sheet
ANALOG MUX- SPI B/ I2C, LVDS VALID, SYS RESET OUT (OPTIONAL): C136 R271 R272 TP4 U30
ANALOG MUX - LIN/UARTB: C135 R253 R274 R275 U24

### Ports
DCA_LP_FTDI_HOST_INTR_1 (bidir), DCA_LP_FTDI_SPIA_CLK (bidir), DCA_LP_FTDI_SPIA_CS (bidir), DCA_LP_FTDI_SPIA_MISO (bidir), DCA_LP_FTDI_SPIA_MOSI (bidir), DCA_LP_HOST_INTR_1, DCA_LP_SPIA_CLK (out), DCA_LP_SPIA_CS (out), DCA_LP_SPIA_MISO (in), DCA_LP_SPIA_MOSI (out), FTDI_HOST_INTR_1 (bidir), FTDI_SPI_CLK (bidir), FTDI_SPI_CS (bidir), FTDI_SPI_MISO (bidir), FTDI_SPI_MOSI (bidir), HOST_CLK_REQ_SPIB_MISO (bidir), I2C_SCL (bidir), I2C_SCL_SPIB_CLK (bidir), I2C_SDA (bidir), I2C_SDA_SPIB_MOSI (bidir), LIN_PHY_RX (in), LIN_PHY_RX_UARTB_TX (bidir), LIN_PHY_TX (out), LIN_PHY_TX_UARTB_RX (bidir), MUX_CTRL_FTDI_DCA_SPIA (in), MUX_CTRL_LIN_UARTB (in), MUX_CTRL_SPIB_I2C_SYS_RST_HOST_CLK_REQ (in), SPIB_CLK (bidir), SPIB_CS0_N (bidir), SPIB_MISO (bidir), SPIB_MOSI (bidir), SYS_RST_OUT (bidir), SYS_RST_OUT_SPIB_CS0_N (bidir), UARTB_RX (in), UARTB_RX (out), UARTB_TX (out)

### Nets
GND: C56.2 C135.2 C136.2 R10.2 R272.1 U24.5(GND) U28.3(NC) U28.5(GND) U30.6(GND)
VCC_3V3: C56.1 C135.1 C136.1 R12.1 R253.2 R271.2 R274.2 R275.2 U24.10(V+) U28.8(VCC) U30.14(V+)
DCA_LP_FTDI_HOST_INTR_1: U28.10(COM5) ; port DCA_LP_FTDI_HOST_INTR_1
DCA_LP_FTDI_SPIA_CLK: U28.4(COM1) ; port DCA_LP_FTDI_SPIA_CLK
DCA_LP_FTDI_SPIA_CS: U28.6(COM2) ; port DCA_LP_FTDI_SPIA_CS
DCA_LP_FTDI_SPIA_MISO: U28.7(COM3) ; port DCA_LP_FTDI_SPIA_MISO
DCA_LP_FTDI_SPIA_MOSI: U28.9(COM4) ; port DCA_LP_FTDI_SPIA_MOSI
DCA_LP_HOST_INTR_1: U28.19(NC5) ; port DCA_LP_HOST_INTR_1
DCA_LP_SPIA_CLK: U28.2(NC1) ; port DCA_LP_SPIA_CLK
DCA_LP_SPIA_CS: U28.1(NC2) ; port DCA_LP_SPIA_CS
DCA_LP_SPIA_MISO: U28.23(NC3) ; port DCA_LP_SPIA_MISO
DCA_LP_SPIA_MOSI: U28.21(NC4) ; port DCA_LP_SPIA_MOSI
FTDI_HOST_INTR_1: U28.18(NO5) ; port FTDI_HOST_INTR_1
FTDI_SPI_CLK: U28.11(NO1) ; port FTDI_SPI_CLK
FTDI_SPI_CS: U28.13(NO2) ; port FTDI_SPI_CS
FTDI_SPI_MISO: U28.15(NO3) ; port FTDI_SPI_MISO
FTDI_SPI_MOSI: U28.17(NO4) ; port FTDI_SPI_MOSI
HOST_CLK_REQ: TP4.1 U30.9(NC3)
HOST_CLK_REQ_SPIB_MISO: U30.7(COM3) ; port HOST_CLK_REQ_SPIB_MISO
I2C_SCL: U30.16(NC1) ; port I2C_SCL
I2C_SCL_SPIB_CLK: U30.2(COM1) ; port I2C_SCL_SPIB_CLK
I2C_SDA: U30.3(NC2) ; port I2C_SDA
I2C_SDA_SPIB_MOSI: U30.5(COM2) ; port I2C_SDA_SPIB_MOSI
LIN_PHY_RX: U24.1(NC1) ; port LIN_PHY_RX
LIN_PHY_RX_UARTB_TX: U24.9(COM1) ; port LIN_PHY_RX_UARTB_TX
LIN_PHY_TX: U24.3(NC2) ; port LIN_PHY_TX
LIN_PHY_TX_UARTB_RX: U24.6(COM2) ; port LIN_PHY_TX_UARTB_RX
MUX_CTRL_FTDI_DCA_SPIA: R12.2 U28.14(IN2) U28.24(IN1) ; port MUX_CTRL_FTDI_DCA_SPIA
MUX_CTRL_LIN_UARTB: R253.1 U24.7(IN2) U24.8(IN1) ; port MUX_CTRL_LIN_UARTB
MUX_CTRL_SPIB_I2C_SYS_RST_HOST_CLK_REQ: R271.1 U30.15(IN) ; port MUX_CTRL_SPIB_I2C_SYS_RST_HOST_CLK_REQ
SPI_MUX_ENn: R10.1 U28.20(~{EN})
SPIB_CLK: U30.1(NO1) ; port SPIB_CLK
SPIB_CS0_N: U30.11(NO4) ; port SPIB_CS0_N
SPIB_MISO: U30.8(NO3) ; port SPIB_MISO
SPIB_MOSI: U30.4(NO2) ; port SPIB_MOSI
SYS_RST_OUT: U30.12(NC4) ; port SYS_RST_OUT
SYS_RST_OUT_SPIB_CS0_N: U30.10(COM4) ; port SYS_RST_OUT_SPIB_CS0_N
UARTB_RX: R275.1 U24.4(NO2) ; port UARTB_RX
UARTB_TX: R274.1 U24.2(NO1) ; port UARTB_TX
NetR272_2: R272.2 U30.13(~{EN})

Not connected (* = marked no-connect by the designer): U28 12(COM6)* 16(NO6)* 22(NC6)*

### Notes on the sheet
- ANALOG MUX SPIA- DCA/FTDI
- Design note:
- Tested across RL=50Ohm,CL=35pF
- (near U28) Propagation delay of the MUX is typ 18.1ns

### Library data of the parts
C56 = CMP-0006356-2: as C34 on sheet PROC182A_Decoupling_caps- QSPI Flash
C135 C136 = CMP-0006356-2: as C40 on sheet PROC182A_Analog_Mux_SOP_Ctrl
R10 R12 R253 R271 = CMP-0025958-3: as R2 on sheet PROC182A_Temp_Current_sensors_EPROM
R272 = CMP-0026739-1: as R6 on sheet PROC182A_Analog_Mux_SOP_Ctrl
R274 R275 = CMP-0025950-3: RES, 100 k, 1%, 0.063 W, AEC-Q200 Grade 0, 0402; Manufacturer: Vishay-Dale; Power_W: 63mW; TempCo: 100 ppm/C; Value: 100k; EIA_Code: E96; SizeX_mm: 1; SizeY_mm: 0.5; SizeZ_mm: 0.6; Value2: 0.063W; AEC Qualified: Y; VDC_V: 50V; AEC Category: Q200; AEC Grade: 0
TP4 = CMP-0078143-3: TEST POINT.  No entry in BOM.
U24 = CMP-0067410-1: as U16 on sheet PROC182A_Analog_Mux_SOP_Ctrl
U28 = CMP-0092155-1: 3.3-V, 2:1 (SPDT), 6-channel analog multiplexer with 1.8-V compatible control inputs 24-TSSOP -40 to 85; Manufacturer: Texas Instruments; Max Supply Voltage: 3.6V; -3Db Bandwith: 240MHz; Standoff Height: 0.05mm; Category 9E37533Dafe045F0: Logic, Standard; SizeZ_mm: 1.2mm; On State Resistance: 4.4Ω; Category Aef863F29A99753F: Switches; AEC Qualified: No; Category 9E07530Daf1645C0: Semiconductors and Actives; Min Supply Voltage: 1.65V; Nominal Supply Current: 0.01-0.04uA; PositionCount: 6
U30 = CMP-0067415-1: as U4 on sheet PROC182A_Analog_Mux_SOP_Ctrl

## Sheet PROC182A_XDS110_Interface.SchDoc: XDS110_INTERFACE
size 431 x 279 mm; Date: Not shown in title block; ApprovedBy: Not shown in title block; CheckedBy: Not shown in title block; Author: Not shown in title block; CompanyName: Not shown in title block; DrawnBy: Mistral; Engineer: Not shown in title block; Organization: Not shown in title block; Address1: Not shown in title block; Address2: Not shown in title block; Address3: Not shown in title block; Address4: Not shown in title block; DocumentNumber: 12; Revision: Use project parameter SCH_Rev; SheetNumber: 11; SheetTotal: 17; PageSetup: Record=PageOptions¦CenterHorizontal=True¦CenterVertical=True¦PrintScale=1.00¦XCorrection=1.00¦YCorrection=1.00¦PrintKind=0¦BorderSize=5000000¦LeftOffset=0¦BottomOffset=0¦Orientation=2¦PaperLength=1000¦PaperWidth=1000¦Scale=100¦PaperSource=15¦PrintQuality=600¦MediaType=1¦DitherType=10¦PaperKind=Letter¦PrintScaleMode=1
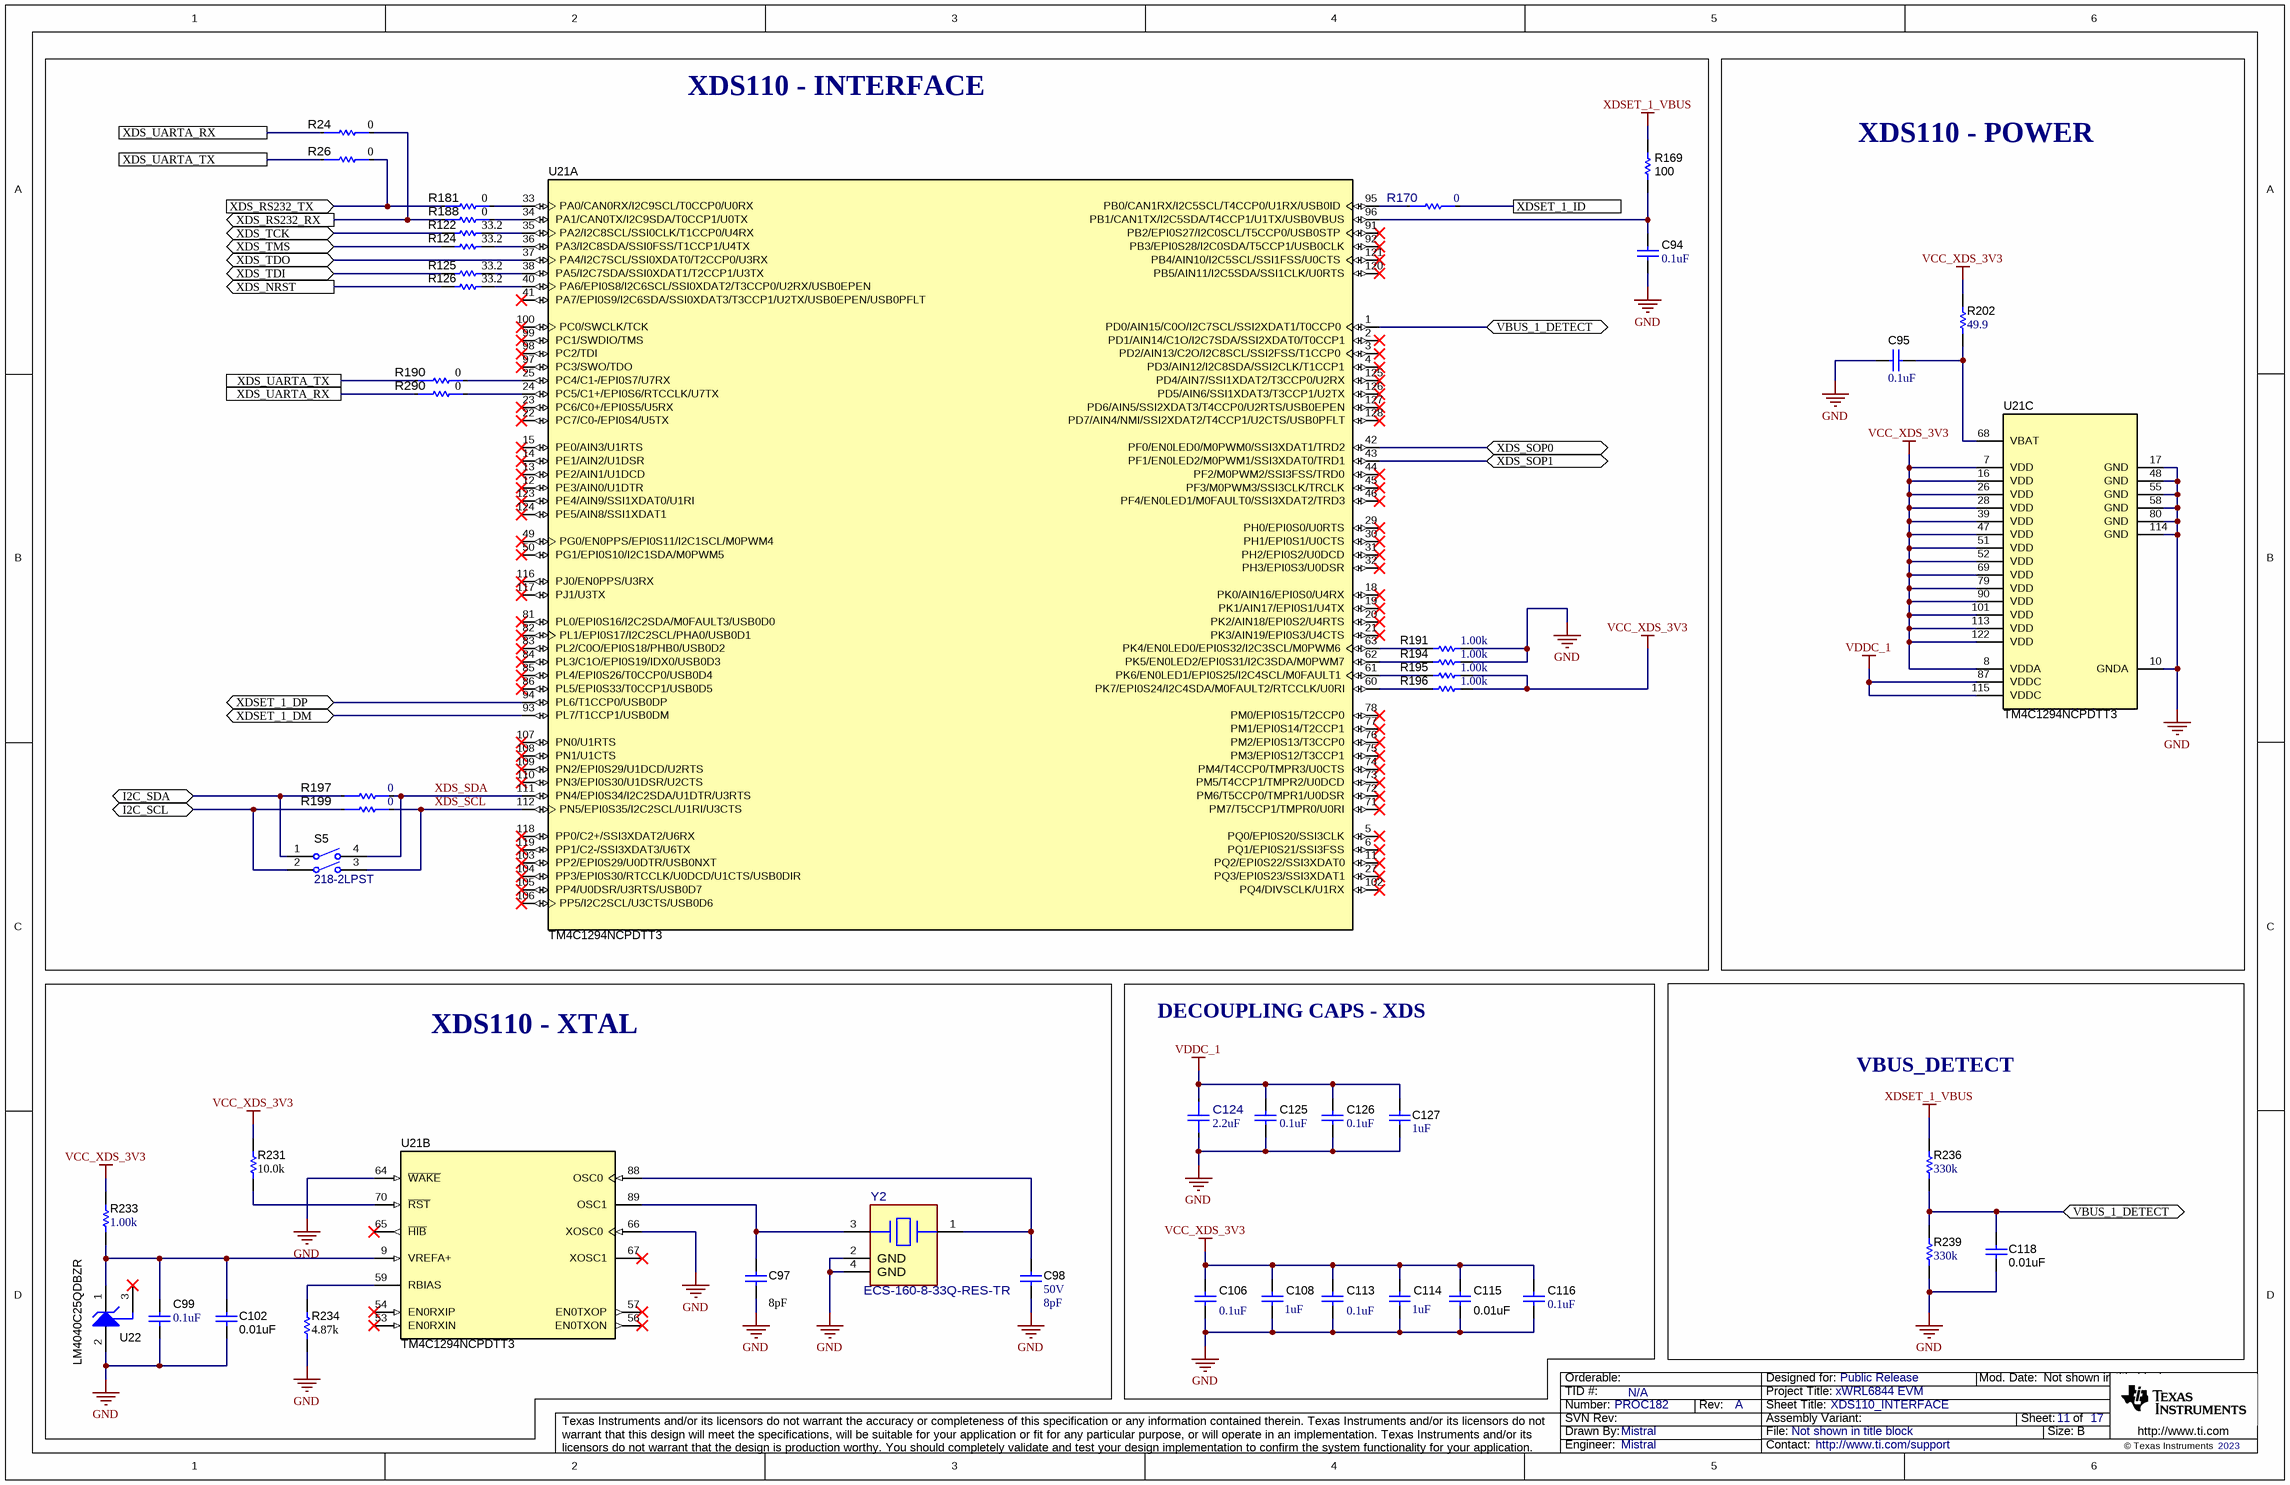
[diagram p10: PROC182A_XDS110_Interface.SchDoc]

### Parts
C94  ValueDisplayed: 0.1uF  [0402]  (hidden comment: GCM155R71H104KE02D)
C95  ValueDisplayed: 0.1uF  [0402]  (hidden comment: GCM155R71H104KE02D)
C97  ValueDisplayed: 8pF  [0402L]  (hidden comment: CC0402DRNPO9BN8R0)
C98  VDC_V: 50V  ValueDisplayed: 8pF  [0402L]  (hidden comment: CC0402DRNPO9BN8R0)
C99  ValueDisplayed: 0.1uF  [0402]  (hidden comment: GCM155R71H104KE02D)
C102  ValueDisplayed: 0.01uF  [0402L]  (hidden comment: GCM155R71E103KA37D)
C106  ValueDisplayed: 0.1uF  [0402]  (hidden comment: GCM155R71H104KE02D)
C108  ValueDisplayed: 1uF  [0402_070]  (hidden comment: GCM155C71A105KE38D)
C113  ValueDisplayed: 0.1uF  [0402]  (hidden comment: GCM155R71H104KE02D)
C114  ValueDisplayed: 1uF  [0402_070]  (hidden comment: GCM155C71A105KE38D)
C115  ValueDisplayed: 0.01uF  [0402L]  (hidden comment: GCM155R71E103KA37D)
C116  ValueDisplayed: 0.1uF  [0402]  (hidden comment: GCM155R71H104KE02D)
C118  ValueDisplayed: 0.01uF  [0402L]  (hidden comment: GCM155R71E103KA37D)
C124  ValueDisplayed: 2.2uF  [FP-GRT155C71A225KE13D_0402-MFG]  (hidden comment: GRT155C71A225KE13D)
C125  ValueDisplayed: 0.1uF  [0402]  (hidden comment: GCM155R71H104KE02D)
C126  ValueDisplayed: 0.1uF  [0402]  (hidden comment: GCM155R71H104KE02D)
C127  ValueDisplayed: 1uF  [0402_070]  (hidden comment: GCM155C71A105KE38D)
R24  value 0  [FP-ERJ-2GE0R00X_0402-MFG]  (hidden comment: ERJ-2GE0R00X)
R26  value 0  [FP-ERJ-2GE0R00X_0402-MFG]  (hidden comment: ERJ-2GE0R00X)
R122  ValueDisplayed: 33.2  [0402]  (hidden comment: CRCW040233R2FKED)
R124  ValueDisplayed: 33.2  [0402]  (hidden comment: CRCW040233R2FKED)
R125  ValueDisplayed: 33.2  [0402]  (hidden comment: CRCW040233R2FKED)
R126  ValueDisplayed: 33.2  [0402]  (hidden comment: CRCW040233R2FKED)
R169  ValueDisplayed: 100  [0402L]  (hidden comment: ERJ-2GEJ101X)
R170  value 0  [FP-ERJ-2GE0R00X_0402-MFG]  (hidden comment: ERJ-2GE0R00X)
R181  value 0  [FP-ERJ-2GE0R00X_0402-MFG]  (hidden comment: ERJ-2GE0R00X)
R188  value 0  [FP-ERJ-2GE0R00X_0402-MFG]  (hidden comment: ERJ-2GE0R00X)
R190  value 0  [FP-ERJ-2GE0R00X_0402-MFG]  (hidden comment: ERJ-2GE0R00X)
R191  ValueDisplayed: 1.00k  [0402]  (hidden comment: ERJ-2RKF1001X)
R194  ValueDisplayed: 1.00k  [0402]  (hidden comment: ERJ-2RKF1001X)
R195  ValueDisplayed: 1.00k  [0402]  (hidden comment: ERJ-2RKF1001X)
R196  ValueDisplayed: 1.00k  [0402]  (hidden comment: ERJ-2RKF1001X)
R197  value 0  [FP-ERJ-2GE0R00X_0402-MFG]  (hidden comment: ERJ-2GE0R00X)
R199  value 0  [FP-ERJ-2GE0R00X_0402-MFG]  (hidden comment: ERJ-2GE0R00X)
R202  ValueDisplayed: 49.9  [0402L]  (hidden comment: CRCW040249R9FKED)
R231  ValueDisplayed: 10.0k  [0402L]  (hidden comment: CRCW040210K0FKED)
R233  ValueDisplayed: 1.00k  [0402]  (hidden comment: ERJ-2RKF1001X)
R234  ValueDisplayed: 4.87k  [0402L]  (hidden comment: CRCW04024K87FKED)
R236  ValueDisplayed: 330k  [0402L]  (hidden comment: CRCW0402330KFKED)
R239  ValueDisplayed: 330k  [0402L]  (hidden comment: CRCW0402330KFKED)
R290  value 0  [FP-ERJ-2GE0R00X_0402-MFG]  (hidden comment: ERJ-2GE0R00X)
S5  218-2LPST  [SW_218-2LP]
U21  TM4C1294NCPDTT3  [PDT0128A]  (parts A,B,C of 3)
U22  LM4040C25QDBZR  [DBZ0003A_N]
Y2  ECS-160-8-33Q-RES-TR  [FP-ECS-160-8-33Q-RES-TR_SMT4_3MM2_2MM5-MFG]

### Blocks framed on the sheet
XDS110 - INTERFACE: C94 R24 R26 R122 R124-R126 R169 R170 R181 R188 R190 R191 R194-R197 R199 R290 S5 U21
XDS110 - POWER: C95 R202 U21
XDS110 - XTAL: C97-C99 C102 R231 R233 R234 U21 U22 Y2
DECOUPLING CAPS - XDS: C106 C108 C113-C116 C124-C127
VBUS_DETECT: C118 R236 R239

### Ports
I2C_SCL (bidir), I2C_SDA (bidir), VBUS_1_DETECT (bidir), XDS_NRST (out), XDS_RS232_RX (out), XDS_RS232_TX (in), XDS_SOP0 (bidir), XDS_SOP1 (bidir), XDS_TCK (bidir), XDS_TDI (bidir), XDS_TDO (bidir), XDS_TMS (bidir), XDS_UARTA_RX, XDS_UARTA_TX, XDSET_1_DM (bidir), XDSET_1_DP (bidir), XDSET_1_ID

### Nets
GND: C94.2 C95.1 C97.1 C98.1 C99.1 C102.1 C106.1 C108.2 C113.1 C114.2 C115.2 C116.1 C118.1 C124.2 C125.1 C126.1 C127.2 R191.2 R194.2 R234.1 R239.1 U21.10(GNDA) U21.17(GND) U21.48(GND) U21.55(GND) U21.58(GND) U21.64(~{WAKE}) U21.66(XOSC0) U21.80(GND) U21.114(GND) U22.2(ANODE) Y2.2(GND) Y2.4(GND)
VCC_XDS_3V3: C106.2 C108.1 C113.2 C114.1 C115.1 C116.2 R195.2 R196.2 R202.1 R231.2 R233.2 U21.7(VDD) U21.8(VDDA) U21.16(VDD) U21.26(VDD) U21.28(VDD) U21.39(VDD) U21.47(VDD) U21.51(VDD) U21.52(VDD) U21.69(VDD) U21.79(VDD) U21.90(VDD) U21.101(VDD) U21.113(VDD) U21.122(VDD)
VDDC_1: C124.1 C125.2 C126.2 C127.1 U21.87(VDDC) U21.115(VDDC)
XDSET_1_VBUS: R169.2 R236.2
I2C_SCL: R199.1 S5.2 ; port I2C_SCL
I2C_SDA: R197.1 S5.1 ; port I2C_SDA
VBUS_1_DETECT: C118.2 R236.1 R239.2 U21.1(PD0/AIN15/C0O/I2C7SCL/SSI2XDAT1/T0CCP0) ; port VBUS_1_DETECT
XDS_NRST: R126.2 ; port XDS_NRST
XDS_RS232_RX: R24.2 R188.1 ; port XDS_RS232_RX
XDS_RS232_TX: R26.2 R181.1 ; port XDS_RS232_TX
XDS_SCL: R199.2 S5.3 U21.112(PN5/EPI0S35/I2C2SCL/U1RI/U3CTS)
XDS_SDA: R197.2 S5.4 U21.111(PN4/EPI0S34/I2C2SDA/U1DTR/U3RTS)
XDS_SOP0: U21.42(PF0/EN0LED0/M0PWM0/SSI3XDAT1/TRD2) ; port XDS_SOP0
XDS_SOP1: U21.43(PF1/EN0LED2/M0PWM1/SSI3XDAT0/TRD1) ; port XDS_SOP1
XDS_TCK: R122.2 ; port XDS_TCK
XDS_TDI: R125.2 ; port XDS_TDI
XDS_TDO: U21.37(PA4/I2C7SCL/SSI0XDAT0/T2CCP0/U3RX) ; port XDS_TDO
XDS_TMS: R124.2 ; port XDS_TMS
XDS_UARTA_RX: R24.1 R290.1 ; port XDS_UARTA_RX
XDS_UARTA_TX: R26.1 R190.1 ; port XDS_UARTA_TX
XDSET_1_DM: U21.93(PL7/T1CCP1/USB0DM) ; port XDSET_1_DM
XDSET_1_DP: U21.94(PL6/T1CCP0/USB0DP) ; port XDSET_1_DP
XDSET_1_ID: R170.2 ; port XDSET_1_ID
NetC94_1: C94.1 R169.1 U21.96(PB1/CAN1TX/I2C5SDA/T4CCP1/U1TX/USB0VBUS)
NetC95_2: C95.2 R202.2 U21.68(VBAT)
NetC97_2: C97.2 U21.89(OSC1) Y2.3(OUT/IN)
NetC98_2: C98.2 U21.88(OSC0) Y2.1(IN/OUT)
NetC99_2: C99.2 C102.2 R233.1 U21.9(VREFA+) U22.1(CATHODE)
NetR122_1: R122.1 U21.35(PA2/I2C8SCL/SSI0CLK/T1CCP0/U4RX)
NetR124_1: R124.1 U21.36(PA3/I2C8SDA/SSI0FSS/T1CCP1/U4TX)
NetR125_1: R125.1 U21.38(PA5/I2C7SDA/SSI0XDAT1/T2CCP1/U3TX)
NetR126_1: R126.1 U21.40(PA6/EPI0S8/I2C6SCL/SSI0XDAT2/T3CCP0/U2RX/USB0EPEN)
NetR170_1: R170.1 U21.95(PB0/CAN1RX/I2C5SCL/T4CCP0/U1RX/USB0ID)
NetR181_2: R181.2 U21.33(PA0/CAN0RX/I2C9SCL/T0CCP0/U0RX)
NetR188_2: R188.2 U21.34(PA1/CAN0TX/I2C9SDA/T0CCP1/U0TX)
NetR190_2: R190.2 U21.25(PC4/C1-/EPI0S7/U7RX)
NetR191_1: R191.1 U21.63(PK4/EN0LED0/EPI0S32/I2C3SCL/M0PWM6)
NetR194_1: R194.1 U21.62(PK5/EN0LED2/EPI0S31/I2C3SDA/M0PWM7)
NetR195_1: R195.1 U21.61(PK6/EN0LED1/EPI0S25/I2C4SCL/M0FAULT1)
NetR196_1: R196.1 U21.60(PK7/EPI0S24/I2C4SDA/M0FAULT2/RTCCLK/U0RI)
NetR231_1: R231.1 U21.70(~{RST})
NetR234_2: R234.2 U21.59(RBIAS)
NetR290_2: R290.2 U21.24(PC5/C1+/EPI0S6/RTCCLK/U7TX)

Not connected (* = marked no-connect by the designer): U21 2(PD1/AIN14/C1O/I2C7SDA/SSI2XDAT0/T0CCP1)* 3(PD2/AIN13/C2O/I2C8SCL/SSI2FSS/T1CCP0)* 4(PD3/AIN12/I2C8SDA/SSI2CLK/T1CCP1)* 5(PQ0/EPI0S20/SSI3CLK)* 6(PQ1/EPI0S21/SSI3FSS)* 11(PQ2/EPI0S22/SSI3XDAT0)* 12(PE3/AIN0/U1DTR)* 13(PE2/AIN1/U1DCD)* 14(PE1/AIN2/U1DSR)* 15(PE0/AIN3/U1RTS)* 18(PK0/AIN16/EPI0S0/U4RX)* 19(PK1/AIN17/EPI0S1/U4TX)* 20(PK2/AIN18/EPI0S2/U4RTS)* 21(PK3/AIN19/EPI0S3/U4CTS)* 22(PC7/C0-/EPI0S4/U5TX)* 23(PC6/C0+/EPI0S5/U5RX)* 27(PQ3/EPI0S23/SSI3XDAT1)* 29(PH0/EPI0S0/U0RTS)* 30(PH1/EPI0S1/U0CTS)* 31(PH2/EPI0S2/U0DCD)* 32(PH3/EPI0S3/U0DSR)* 41(PA7/EPI0S9/I2C6SDA/SSI0XDAT3/T3CCP1/U2TX/USB0EPEN/USB0PFLT)* 44(PF2/M0PWM2/SSI3FSS/TRD0)* 45(PF3/M0PWM3/SSI3CLK/TRCLK)* 46(PF4/EN0LED1/M0FAULT0/SSI3XDAT2/TRD3)* 49(PG0/EN0PPS/EPI0S11/I2C1SCL/M0PWM4)* 50(PG1/EPI0S10/I2C1SDA/M0PWM5)* 53(EN0RXIN)* 54(EN0RXIP)* 56(EN0TXON)* 57(EN0TXOP)* 65(~{HIB})* 67(XOSC1)* 71(PM7/T5CCP1/TMPR0/U0RI)* 72(PM6/T5CCP0/TMPR1/U0DSR)* 73(PM5/T4CCP1/TMPR2/U0DCD)* 74(PM4/T4CCP0/TMPR3/U0CTS)* 75(PM3/EPI0S12/T3CCP1)* 76(PM2/EPI0S13/T3CCP0)* 77(PM1/EPI0S14/T2CCP1)* 78(PM0/EPI0S15/T2CCP0)* 81(PL0/EPI0S16/I2C2SDA/M0FAULT3/USB0D0)* 82(PL1/EPI0S17/I2C2SCL/PHA0/USB0D1)* 83(PL2/C0O/EPI0S18/PHB0/USB0D2)* 84(PL3/C1O/EPI0S19/IDX0/USB0D3)* 85(PL4/EPI0S26/T0CCP0/USB0D4)* 86(PL5/EPI0S33/T0CCP1/USB0D5)* 91(PB2/EPI0S27/I2C0SCL/T5CCP0/USB0STP)* 92(PB3/EPI0S28/I2C0SDA/T5CCP1/USB0CLK)* 97(PC3/SWO/TDO)* 98(PC2/TDI)* 99(PC1/SWDIO/TMS)* 100(PC0/SWCLK/TCK)* 102(PQ4/DIVSCLK/U1RX)* 103(PP2/EPI0S29/U0DTR/USB0NXT)* 104(PP3/EPI0S30/RTCCLK/U0DCD/U1CTS/USB0DIR)* 105(PP4/U0DSR/U3RTS/USB0D7)* 106(PP5/I2C2SCL/U3CTS/USB0D6)* 107(PN0/U1RTS)* 108(PN1/U1CTS)* 109(PN2/EPI0S29/U1DCD/U2RTS)* 110(PN3/EPI0S30/U1DSR/U2CTS)* 116(PJ0/EN0PPS/U3RX)* 117(PJ1/U3TX)* 118(PP0/C2+/SSI3XDAT2/U6RX)* 119(PP1/C2-/SSI3XDAT3/U6TX)* 120(PB5/AIN11/I2C5SDA/SSI1CLK/U0RTS)* 121(PB4/AIN10/I2C5SCL/SSI1FSS/U0CTS)* 123(PE4/AIN9/SSI1XDAT0/U1RI)* 124(PE5/AIN8/SSI1XDAT1)* 125(PD4/AIN7/SSI1XDAT2/T3CCP0/U2RX)* 126(PD5/AIN6/SSI1XDAT3/T3CCP1/U2TX)* 127(PD6/AIN5/SSI2XDAT3/T4CCP0/U2RTS/USB0EPEN)* 128(PD7/AIN4/NMI/SSI2XDAT2/T4CCP1/U2CTS/USB0PFLT)*; U22 3(NC)*

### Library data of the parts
C94 C95 C99 C106 C113 C116 C125 C126 = CMP-0006356-2: as C40 on sheet PROC182A_Analog_Mux_SOP_Ctrl
C97 = CMP-0860185-1: CAP, CERM, 8 pF, 50 V,+/- 6.25%, C0G/NP0, 0402; Manufacturer: Yageo; Cap_Case: 0402; Polarized: N; TaMax_C: 125°C; Value2: 50V; SizeY_mm: 0.5; SizeX_mm: 1; Value: 8pF; AEC Category: Q200; U/M: EA; SizeAreaWB_mm2: 3; TaMin_C: -55°C; SizeZ_mm: 0.6
C98 = CMP-0860185-1: CAP, CERM, 8 pF, 50 V,+/- 6.25%, C0G/NP0, 0402; Manufacturer: Yageo; Cap_Case: 0402; Polarized: N; TaMax_C: 125°C; SizeY_mm: 0.5; SizeX_mm: 1; Value: 8pF; AEC Category: Q200; U/M: EA; SizeAreaWB_mm2: 3; TaMin_C: -55°C; SizeZ_mm: 0.6
C102 C115 C118 = CMP-0006352-2: as C128 on sheet PROC182A_Decoupling_caps- QSPI Flash
C108 C114 C127 = CMP-0006349-2: CAP, CERM, 1 uF, 10 V, +/- 10%, X7S, AEC-Q200 Grade 1, 0402; Manufacturer: MuRata; Polarized: N; Value: 1uF; U/M: EA; Cap_F: 1µF; Value1: Unknown; VDC_V: 10V; TaMin_C: -55°C; TaMax_C: 125°C; Cap_Case: 0402; SizeArea_mm2: 0.5; SizeAreaWB_mm2: 3; SizeX_mm: 1; SizeZ_mm: 0.7; AEC Category: Q200; AEC Qualified: Y
C124 = CMP-0094968-1: Multi-Layer Ceramic Capacitor 2.2uF 10V X7S ±10% 0402 Paper T/R; Manufacturer: Murata; TempCo: 22%; Value: 2.2µF; SizeZ_mm: 0.7mm; AEC Qualified: Yes; AEC Grade: Grade 1
R24 R26 R170 R181 R188 R190 R197 R199 R290 = CMP-0002710-1: as R25 on sheet PROC182A_Temp_Current_sensors_EPROM
R122 R124-R126 = CMP-0026299-2: RES, 33.2, 1%, 0.063 W, AEC-Q200 Grade 0, 0402; Manufacturer: Vishay-Dale; Power_W: 63mW; TempCo: 100 ppm/C; Value_Code: 33R2; Value: 33.2; EIA_Code: E96; SizeX_mm: 1; SizeY_mm: 0.5; SizeZ_mm: 0.6; Value2: 0.063W; AEC Qualified: Y; AEC Grade: 0; AEC Category: Q200; VDC_V: 50V
R169 = CMP-0026993-2: RES, 100, 5%, 0.1 W, AEC-Q200 Grade 0, 0402; Manufacturer: Panasonic; Power_W: 100mW; TempCo: 200 ppm/C; Value_Code: 100R; U/M: EA; Value: 100; EIA_Code: E24; SizeX_mm: 1; SizeY_mm: 0.5; SizeZ_mm: 0.6; Value2: 0.1W; AEC Qualified: Y; AEC Grade: 0; AEC Category: Q200
R191 R194-R196 R233 = CMP-0026657-1: as R70 on sheet PROC182A_Analog_Mux_SOP_Ctrl
R202 = CMP-0026404-2: RES, 49.9, 1%, 0.063 W, AEC-Q200 Grade 0, 0402; Manufacturer: Vishay-Dale; Power_W: 63mW; TempCo: 100 ppm/C; Value_Code: 49R9; Value: 49.9; EIA_Code: E96; SizeX_mm: 1; SizeY_mm: 0.5; SizeZ_mm: 0.6; Value2: 0.063W; AEC Qualified: Y; VDC_V: 50V; AEC Category: Q200; AEC Grade: 0
R231 = CMP-0025958-3: as R2 on sheet PROC182A_Temp_Current_sensors_EPROM
R234 = CMP-0026413-2: RES, 4.87 k, 1%, 0.063 W, AEC-Q200 Grade 0, 0402; Manufacturer: Vishay-Dale; Power_W: 63mW; TempCo: 100 ppm/C; Value_Code: 4k87; Value: 4.87k; EIA_Code: E96; SizeX_mm: 1; SizeY_mm: 0.5; SizeZ_mm: 0.6; Value2: 0.063W; AEC Qualified: Y; VDC_V: 50V; AEC Category: Q200; AEC Grade: 0
R236 R239 = CMP-0078210-2: RES, 330 k, 1%, 0.063 W, AEC-Q200 Grade 0, 0402; Manufacturer: Vishay-Dale; SizeArea_mm2: 0.5; AEC Qualified: Y; AEC Category: Q200; Value: 330k; SizeZ_mm: 0.6; TempCo: 100 ppm/C; AEC Grade: 0; Power_W: 63mW; VDC_V: 50V; Value2: 0.063W; SizeX_mm: 1
S5 = CMP-0002230-1: Switch, SPST, 2 Pos, 25mA, 24VDC, SMD; Manufacturer: CTS Electrocomponents; CurrentRating_mA: 25A; PositionCount: 2; VDC_V: 24V; SwitchFunction: Off-On
U21 = CMP-0029856-2: Tiva C Series Microcontroller, 1024 KB Flash, 256 KB SRAM, 12 Bit, 20 Channels, -40 to 105 degC, 128-Pin TQFP (PDT), Green (RoHS & no Sb/Br), Tray; Manufacturer: Texas Instruments; ADC Channels: 20; CPU: ARM Cortex-M4; Flash: 1024 KB; ADC Resolution: 12 Bits; Max Speed: 120 MHz; SRAM: 256 KB; SizeAreaWB_mm2: 324.0; SizeArea_mm2: 256.0; SizeX_mm: 16.0; SizeZ_mm: 1.2; CompType: IC
U22 = CMP-0033001-1: Precision Micropower Shunt Voltage Reference, 0.5% accuracy, 2.5 V, 15 ppm / degC, 15 mA, -40 to 125 degC, 3-pin SOT-23 (DBZ), Green (RoHS & no Sb/Br); Manufacturer: Texas Instruments; Initial Accuracy @ 25/deg C(%): 0.5; Temp Coeff(Typ)(ppm/ degree C): 15; Temp Coeff(Max)(ppm/ degree C): 100; Rating: Catalog; Min Iz for Regulation(uA): 75; VO(V): 2.5
Y2 = CMP-0095014-1: 16 MHz ±15ppm Crystal 8pF 80 Ohms 4-SMD, No Lead; Manufacturer: ECS; Frequency Stability: 50ppm; SizeZ_mm: 0.8mm; Frequency_Fixed: 16MHz; AEC Qualified: Yes; Esr: 80; AEC Grade: Grade 1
